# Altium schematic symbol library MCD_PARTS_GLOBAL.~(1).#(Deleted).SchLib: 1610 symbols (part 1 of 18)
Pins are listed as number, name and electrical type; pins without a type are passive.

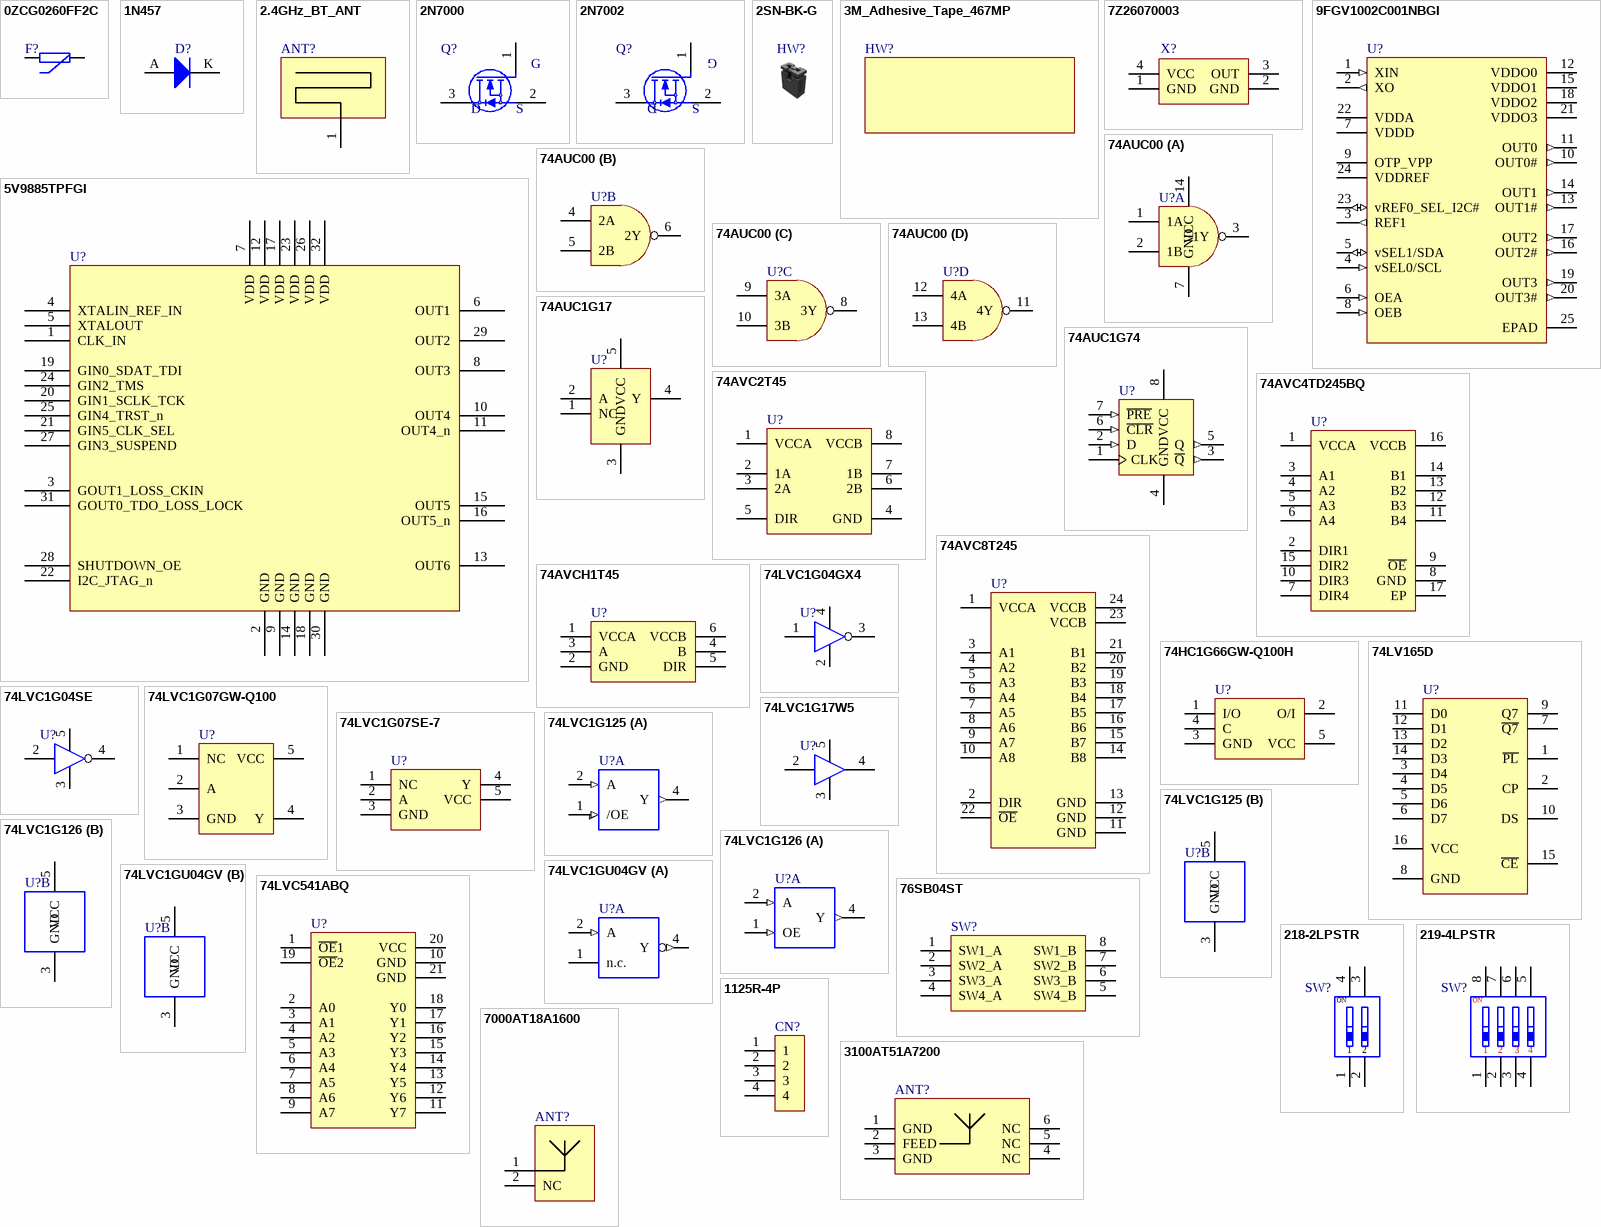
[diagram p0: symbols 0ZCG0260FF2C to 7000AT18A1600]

## 0ZCG0260FF2C
designator F?
pins: 1, 2

## 1N457
designator D?
pins: A, K

## 2.4GHz_BT_ANT
designator ANT?  (no BOM)
pins: 1

## 2N7000
designator Q?
pins: 1 G, 2 S, 3 D

## 2N7002
designator Q?
pins: 1 G, 2 S, 3 D

## 2SN-BK-G
designator HW?

## 3M_Adhesive_Tape_467MP
designator HW?

## 5V9885TPFGI
designator U?
pins: 1 CLK_IN, 2 GND, 3 GOUT1_LOSS_CKIN, 4 XTALIN_REF_IN, 5 XTALOUT, 6 OUT1, 7 VDD, 8 OUT3, 9 GND, 10 OUT4, 11 OUT4_n, 12 VDD, 13 OUT6, 14 GND, 15 OUT5, 16 OUT5_n, 17 VDD, 18 GND, 19 GIN0_SDAT_TDI, 20 GIN1_SCLK_TCK, 21 GIN5_CLK_SEL, 22 I2C_JTAG_n, 23 VDD, 24 GIN2_TMS, 25 GIN4_TRST_n, 26 VDD, 27 GIN3_SUSPEND, 28 SHUTDOWN_OE, 29 OUT2, 30 GND, 31 GOUT0_TDO_LOSS_LOCK, 32 VDD

## 7Z26070003
designator X?
pins: 1 GND, 2 GND, 3 OUT, 4 VCC

## 9FGV1002C001NBGI
designator U?
pins: 1 XIN (in), 2 XO (out), 3 REF1 (out), 4 vSEL0/SCL (in), 5 vSEL1/SDA (io), 6 OEA (in), 7 VDDD (power), 8 OEB (in), 9 OTP_VPP (power), 10 OUT0# (out), 11 OUT0 (out), 12 VDDO0 (power), 13 OUT1# (out), 14 OUT1 (out), 15 VDDO1 (power), 16 OUT2# (out), 17 OUT2 (out), 18 VDDO2 (power), 19 OUT3 (out), 20 OUT3# (out), 21 VDDO3 (power), 22 VDDA (power), 23 vREF0_SEL_I2C# (io), 24 VDDREF (power), 25 EPAD (power)

## 74AUC00
designator U?
part A pins: 1 NC hidden, 1 1A, 2 1B, 3 1Y, 7 GND, 14 VCC
part B pins: 4 2A, 5 2B, 6 2Y
part C pins: 8 3Y, 9 3A, 10 3B
part D pins: 11 4Y, 12 4A, 13 4B

## 74AUC1G17
designator U?
pins: 1 NC, 2 A, 3 GND, 4 Y, 5 VCC

## 74AUC1G74
designator U?
pins: 1 CLK, 2 D (in), 3 ~{Q} (out), 4 GND, 5 Q (out), 6 ~{CLR} (in), 7 ~{PRE} (in), 8 VCC (power)

## 74AVC2T45
designator U?
pins: 1 VCCA, 2 1A, 3 2A, 4 GND, 5 DIR, 6 2B, 7 1B, 8 VCCB

## 74AVC4TD245BQ
designator U?
pins: 1 VCCA, 2 DIR1, 3 A1, 4 A2, 5 A3, 6 A4, 7 DIR4, 8 GND, 9 ~{OE}, 10 DIR3, 11 B4, 12 B3, 13 B2, 14 B1, 15 DIR2, 16 VCCB, 17 EP

## 74AVC8T245
designator U?
pins: 1 VCCA, 2 DIR, 3 A1, 4 A2, 5 A3, 6 A4, 7 A5, 8 A6, 9 A7, 10 A8, 11 GND, 12 GND, 13 GND, 14 B8, 15 B7, 16 B6, 17 B5, 18 B4, 19 B3, 20 B2, 21 B1, 22 ~{OE}, 23 VCCB, 24 VCCB

## 74AVCH1T45
designator U?
pins: 1 VCCA, 2 GND, 3 A, 4 B, 5 DIR, 6 VCCB

## 74HC1G66GW-Q100H
designator U?
pins: 1 I/O, 2 O/I, 3 GND, 4 C, 5 VCC

## 74LV165D
designator U?
pins: 1 ~{PL}, 2 CP, 3 D4, 4 D5, 5 D6, 6 D7, 7 ~{Q7}, 8 GND, 9 Q7, 10 DS, 11 D0, 12 D1, 13 D2, 14 D3, 15 ~{CE}, 16 VCC

## 74LVC1G04GX4
designator U?
pins: 1 NC hidden, 1 A, 2 GND, 3 Y, 4 VCC

## 74LVC1G04SE
designator U?
pins: 1 NC hidden, 2 A, 3 GND, 4 Y, 5 VCC

## 74LVC1G07GW-Q100
designator U?
pins: 1 NC, 2 A, 3 GND, 4 Y, 5 VCC

## 74LVC1G07SE-7
designator U?
pins: 1 NC, 2 A, 3 GND, 4 Y, 5 VCC

## 74LVC1G17W5
designator U?
pins: 1 NC hidden, 2 A, 3 GND, 4 Y, 5 VCC

## 74LVC1G125
designator U?
part A pins: 1 /OE (in), 2 A (in), 4 Y (out)
part B pins: 3 GND (power), 5 VCC

## 74LVC1G126
designator U?
part A pins: 1 OE (in), 2 A (in), 4 Y (out)
part B pins: 3 GND (power), 5 VCC

## 74LVC1GU04GV
designator U?
part A pins: 1 n.c., 2 A (in), 4 Y (out)
part B pins: 3 GND (power), 5 VCC (power)

## 74LVC541ABQ
designator U?
pins: 1 ~{OE}1, 2 A0, 3 A1, 4 A2, 5 A3, 6 A4, 7 A5, 8 A6, 9 A7, 10 GND, 11 Y7, 12 Y6, 13 Y5, 14 Y4, 15 Y3, 16 Y2, 17 Y1, 18 Y0, 19 ~{OE}2, 20 VCC, 21 GND

## 76SB04ST
designator SW?
pins: 1 SW1_A, 2 SW2_A, 3 SW3_A, 4 SW4_A, 5 SW4_B, 6 SW3_B, 7 SW2_B, 8 SW1_B

## 218-2LPSTR
designator SW?
pins: 1, 2, 3, 4

## 219-4LPSTR
designator SW?
pins: 1, 2, 3, 4, 5, 6, 7, 8

## 1125R-4P
designator CN?
pins: 1, 2, 3, 4

## 3100AT51A7200
designator ANT?
pins: 1 GND, 2 FEED, 3 GND, 4 NC, 5 NC, 6 NC

## 7000AT18A1600
designator ANT?
pins: 1, 2 NC

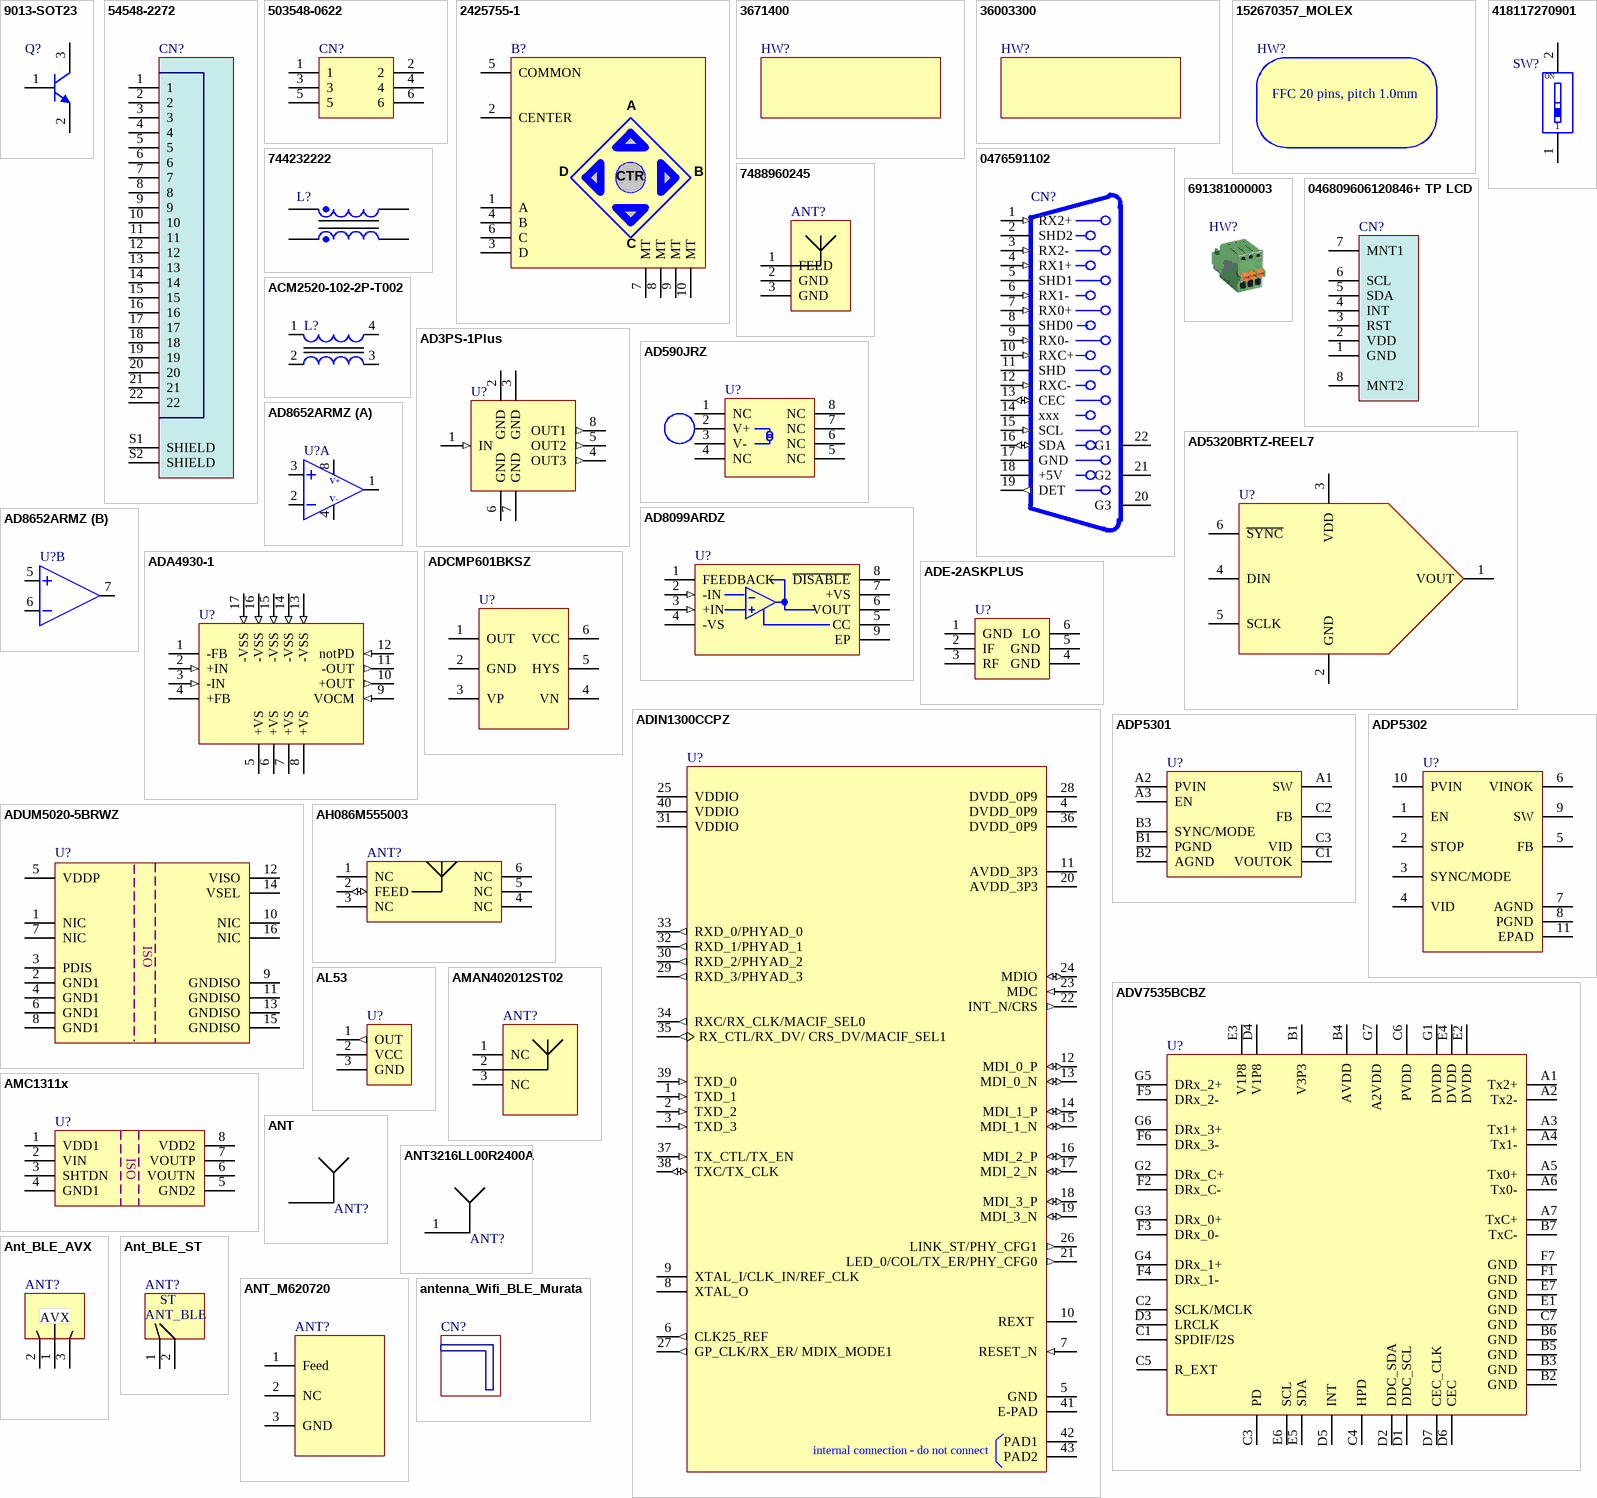
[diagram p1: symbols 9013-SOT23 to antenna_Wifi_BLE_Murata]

## 9013-SOT23
designator Q?
pins: 1 B, 2 E, 3 C

## 54548-2272
designator CN?
pins: 1, 2, 3, 4, 5, 6, 7, 8, 9, 10, 11, 12, 13, 14, 15, 16, 17, 18, 19, 20, 21, 22, S1 SHIELD, S2 SHIELD

## 503548-0622
designator CN?
pins: 1, 2, 3, 4, 5, 6

## 2425755-1
designator B?
pins: 1 A, 2 CENTER, 3 D, 4 B, 5 COMMON, 6 C, 7 MT, 8 MT, 9 MT, 10 MT

## 3671400
designator HW?

## 36003300
designator HW?

## 152670357_MOLEX
designator HW?, comment FFC 20 pins, pitch 1.0mm  (mechanical)

## 0476591102
designator CN?
pins: 1 RX2+ (in), 2 SHD2, 3 RX2- (in), 4 RX1+ (in), 5 SHD1, 6 RX1- (in), 7 RX0+ (in), 8 SHD0, 9 RX0- (in), 10 RXC+ (in), 11 SHD, 12 RXC- (in), 13 CEC (io), 14 xxx, 15 SCL (in), 16 SDA (io), 17 GND, 18 +5V (power), 19 DET (out), 20 G3, 21 G2, 22 G1

## 744232222
designator L?
pins: 1, 2, 3, 4

## 7488960245
designator ANT?
pins: 1 FEED, 2 GND, 3 GND

## 418117270901
designator SW?
pins: 1, 2

## 691381000003
designator HW?

## 046809606120846+ TP LCD
designator CN?
pins: 1 GND, 2 VDD, 3 RST, 4 INT, 5 SDA, 6 SCL, 7 MNT1, 8 MNT2

## ACM2520-102-2P-T002
designator L?
pins: 1, 2, 3, 4

## AD3PS-1Plus
designator U?
pins: 1 IN (in), 2 GND (power), 3 GND (power), 4 OUT3 (out), 5 OUT2 (out), 6 GND (power), 7 GND (power), 8 OUT1 (out)

## AD590JRZ
designator U?
pins: 1 NC, 2 V+, 3 V-, 4 NC, 5 NC, 6 NC, 7 NC, 8 NC

## AD5320BRTZ-REEL7
designator U?
pins: 1 VOUT, 2 GND, 3 VDD, 4 DIN, 5 SCLK, 6 ~{SYNC}

## AD8099ARDZ
designator U?
pins: 1 FEEDBACK, 2 -IN (in), 3 +IN (in), 4 -VS, 5 CC, 6 VOUT, 7 +VS, 8 ~{DISABLE}, 9 EP

## AD8652ARMZ
designator U?
part A pins: 1, 2, 3, 4, 8
part B pins: 5, 6, 7

## ADA4930-1
designator U?
pins: 1 -FB, 2 +IN (in), 3 -IN (in), 4 +FB, 5 +VS, 6 +VS, 7 +VS, 8 +VS, 9 VOCM (in), 10 +OUT (out), 11 -OUT (out), 12 notPD (in), 13 -VSS (in), 14 -VSS (in), 15 -VSS (in), 16 -VSS (in), 17 -VSS (in)

## ADCMP601BKSZ
designator U?
pins: 1 OUT, 2 GND, 3 VP, 4 VN, 5 HYS, 6 VCC

## ADE-2ASKPLUS
designator U?
pins: 1 GND, 2 IF, 3 RF, 4 GND, 5 GND, 6 LO

## ADIN1300CCPZ
designator U?
pins: 1 TXD_1 (in), 2 TXD_2 (in), 3 TXD_3 (in), 4 DVDD_0P9 (power), 5 GND (power), 6 CLK25_REF (out), 7 RESET_N (in), 8 XTAL_O, 9 XTAL_I/CLK_IN/REF_CLK, 10 REXT , 11 AVDD_3P3 (power), 12 MDI_0_P (io), 13 MDI_0_N (io), 14 MDI_1_P (io), 15 MDI_1_N (io), 16 MDI_2_P (io), 17 MDI_2_N (io), 18 MDI_3_P (io), 19 MDI_3_N (io), 20 AVDD_3P3 (power), 21 LED_0/COL/TX_ER/PHY_CFG0 (out), 22 INT_N/CRS (out), 23 MDC (in), 24 MDIO (io), 25 VDDIO (power), 26 LINK_ST/PHY_CFG1 (out), 27 GP_CLK/RX_ER/ MDIX_MODE1  (out), 28 DVDD_0P9 (power), 29 RXD_3/PHYAD_3 (out), 30 RXD_2/PHYAD_2 (out), 31 VDDIO (power), 32 RXD_1/PHYAD_1 (out), 33 RXD_0/PHYAD_0 (out), 34 RXC/RX_CLK/MACIF_SEL0 (out), 35 RX_CTL/RX_DV/ CRS_DV/MACIF_SEL1 (out), 36 DVDD_0P9 (power), 37 TX_CTL/TX_EN  (in), 38 TXC/TX_CLK  (io), 39 TXD_0 (in), 40 VDDIO (power), 41 E-PAD (power), 42 PAD1 (power), 43 PAD2 (power)

## ADP5301
designator U?
pins: A1 SW, A2 PVIN, A3 EN, B1 PGND, B2 AGND, B3 SYNC/MODE, C1 VOUTOK, C2 FB, C3 VID

## ADP5302
designator U?
pins: 1 EN, 2 STOP, 3 SYNC/MODE, 4 VID, 5 FB, 6 VINOK, 7 AGND, 8 PGND, 9 SW, 10 PVIN, 11 EPAD

## ADUM5020-5BRWZ
designator U?
pins: 1 NIC, 2 GND1, 3 PDIS, 4 GND1, 5 VDDP, 6 GND1, 7 NIC, 8 GND1, 9 GNDISO, 10 NIC, 11 GNDISO, 12 VISO, 13 GNDISO, 14 VSEL, 15 GNDISO, 16 NIC

## ADV7535BCBZ
designator U?
pins: A1 Tx2+, A2 Tx2-, A3 Tx1+, A4 Tx1-, A5 Tx0+, A6 Tx0-, A7 TxC+, B1 V3P3, B2 GND, B3 GND, B4 AVDD, B5 GND, B6 GND, B7 TxC-, C1 SPDIF/I2S, C2 SCLK/MCLK, C3 PD, C4 HPD, C5 R_EXT, C6 PVDD, C7 GND, D1 DDC_SCL, D2 DDC_SDA, D3 LRCLK, D4 V1P8, D5 INT, D6 CEC, D7 CEC_CLK, E1 GND, E2 DVDD, E3 V1P8, E4 DVDD, E5 SDA, E6 SCL, E7 GND, F1 GND, F2 DRx_C-, F3 DRx_0-, F4 DRx_1-, F5 DRx_2-, F6 DRx_3-, F7 GND, G1 DVDD, G2 DRx_C+, G3 DRx_0+, G4 DRx_1+, G5 DRx_2+, G6 DRx_3+, G7 A2VDD

## AH086M555003
designator ANT?
pins: 1 NC (hiz), 2 FEED (io), 3 NC (hiz), 4 NC (hiz), 5 NC (hiz), 6 NC (hiz)

## AL53
designator U?
pins: 1 OUT (out), 2 VCC (power), 3 GND (power)

## AMAN402012ST02
designator ANT?
pins: 1 NC, 2, 3 NC

## AMC1311x
designator U?
pins: 1 VDD1, 2 VIN, 3 SHTDN, 4 GND1, 5 GND2, 6 VOUTN, 7 VOUTP, 8 VDD2

## ANT
designator ANT?

## ANT3216LL00R2400A
designator ANT?
pins: 1

## Ant_BLE_AVX
designator ANT?
pins: 1, 2, 3

## Ant_BLE_ST
designator ANT?
pins: 1, 2

## ANT_M620720
designator ANT?
pins: 1 Feed, 2 NC, 3 GND

## antenna_Wifi_BLE_Murata
designator CN?

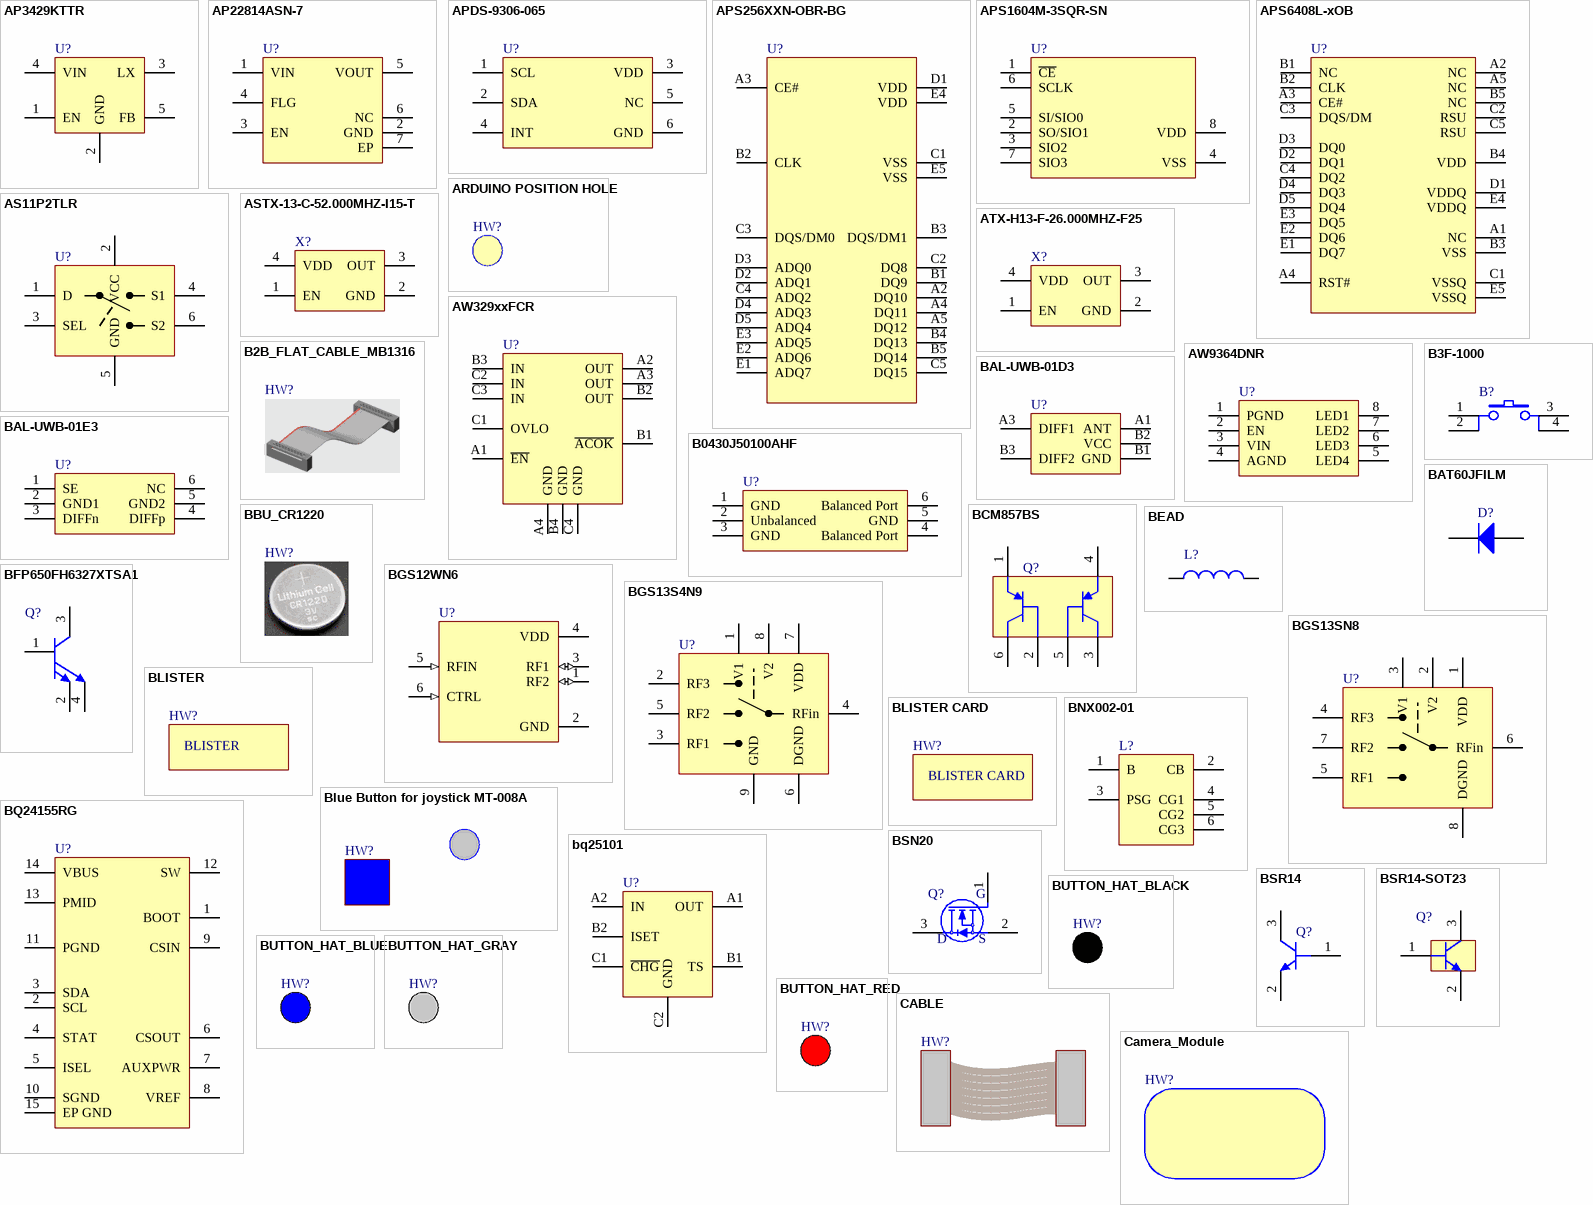
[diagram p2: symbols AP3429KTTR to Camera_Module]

## AP3429KTTR
designator U?
pins: 1 EN, 2 GND, 3 LX, 4 VIN, 5 FB

## AP22814ASN-7
designator U?
pins: 1 VIN, 2 GND, 3 EN, 4 FLG, 5 VOUT, 6 NC, 7 EP

## APDS-9306-065
designator U?
pins: 1 SCL, 2 SDA, 3 VDD, 4 INT, 5 NC, 6 GND

## APS256XXN-OBR-BG
designator U?
pins: A2 DQ10, A3 CE#, A4 DQ11, A5 DQ12, B1 DQ9, B2 CLK, B3 DQS/DM1, B4 DQ13, B5 DQ14, C1 VSS, C2 DQ8, C3 DQS/DM0, C4 ADQ2, C5 DQ15, D1 VDD, D2 ADQ1, D3 ADQ0, D4 ADQ3, D5 ADQ4, E1 ADQ7, E2 ADQ6, E3 ADQ5, E4 VDD, E5 VSS

## APS1604M-3SQR-SN
designator U?
pins: 1 ~{CE}, 2 SO/SIO1, 3 SIO2, 4 VSS, 5 SI/SIO0, 6 SCLK, 7 SIO3, 8 VDD

## APS6408L-xOB
designator U?
pins: A1 NC, A2 NC, A3 CE#, A4 RST#, A5 NC, B1 NC, B2 CLK, B3 VSS, B4 VDD, B5 NC, C1 VSSQ, C2 RSU, C3 DQS/DM, C4 DQ2, C5 RSU, D1 VDDQ, D2 DQ1, D3 DQ0, D4 DQ3, D5 DQ4, E1 DQ7, E2 DQ6, E3 DQ5, E4 VDDQ, E5 VSSQ
1 alternate drawing of the same symbol

## ARDUINO POSITION HOLE
designator HW?  (no BOM)

## AS11P2TLR
designator U?
pins: 1 D, 2 VCC, 3 SEL, 4 S1, 5 GND, 6 S2

## ASTX-13-C-52.000MHZ-I15-T
designator X?
pins: 1 EN, 2 GND, 3 OUT, 4 VDD

## ATX-H13-F-26.000MHZ-F25
designator X?
pins: 1 EN, 2 GND, 3 OUT, 4 VDD

## AW329xxFCR
designator U?
pins: A1 ~{EN}, A2 OUT, A3 OUT, A4 GND, B1 ~{ACOK}, B2 OUT, B3 IN, B4 GND, C1 OVLO, C2 IN, C3 IN, C4 GND

## AW9364DNR
designator U?
pins: 1 PGND, 2 EN, 3 VIN, 4 AGND, 5 LED4, 6 LED3, 7 LED2, 8 LED1

## B2B_FLAT_CABLE_MB1316
designator HW?  (mechanical)

## B3F-1000
designator B?
pins: 1, 2, 3, 4

## B0430J50100AHF
designator U?
pins: 1 GND, 2 Unbalanced, 3 GND, 4 Balanced Port, 5 GND, 6 Balanced Port

## BAL-UWB-01D3
designator U?
pins: A1 ANT, A3 DIFF1, B1 GND, B2 VCC, B3 DIFF2

## BAL-UWB-01E3
designator U?
pins: 1 SE, 2 GND1, 3 DIFFn, 4 DIFFp, 5 GND2, 6 NC

## BAT60JFILM
designator D?
pins: 1 A, 2 K

## BBU_CR1220
designator HW?  (mechanical)

## BCM857BS
designator Q?
pins: 1 E1, 2 B1, 3 C2, 4 E2, 5 B2, 6 C1

## BEAD
designator L?
pins: 1, 2

## BFP650FH6327XTSA1
designator Q?
pins: 1 B, 2 E, 3 C, 4 E

## BGS12WN6
designator U?
pins: 1 RF2 (io), 2 GND (power), 3 RF1 (io), 4 VDD (power), 5 RFIN (in), 6 CTRL (in)

## BGS13S4N9
designator U?
pins: 1 V1, 2 RF3, 3 RF1, 4 RFin, 5 RF2, 6 DGND, 7 VDD, 8 V2, 9 GND

## BGS13SN8
designator U?
pins: 1 VDD, 2 V2, 3 V1, 4 RF3, 5 RF1, 6 RFin, 7 RF2, 8 DGND

## BLISTER
designator HW?  (no BOM)

## BLISTER CARD
designator HW?  (no BOM)

## Blue Button for joystick MT-008A
designator HW?  (mechanical)

## BNX002-01
designator L?
pins: 1 B, 2 CB, 3 PSG, 4 CG1, 5 CG2, 6 CG3

## BQ24155RG
designator U?
pins: 1 BOOT, 2 SCL, 3 SDA, 4 STAT, 5 ISEL, 6 CSOUT, 7 AUXPWR, 8 VREF, 9 CSIN, 10 SGND, 11 PGND, 12 SW, 13 PMID, 14 VBUS, 15 EP GND

## bq25101
designator U?
pins: A1 OUT, A2 IN, B1 TS, B2 ISET, C1 ~{CHG}, C2 GND

## BSN20
designator Q?
pins: 1 G, 2 S, 3 D

## BSR14
designator Q?
pins: 1 B, 2 E, 3 C

## BSR14-SOT23
designator Q?
pins: 1 B, 2 E, 3 C

## BUTTON_HAT_BLACK
designator HW?  (mechanical)

## BUTTON_HAT_BLUE
designator HW?  (mechanical)

## BUTTON_HAT_GRAY
designator HW?  (mechanical)

## BUTTON_HAT_RED
designator HW?  (mechanical)

## CABLE
designator HW?  (mechanical)

## Camera_Module
designator HW?

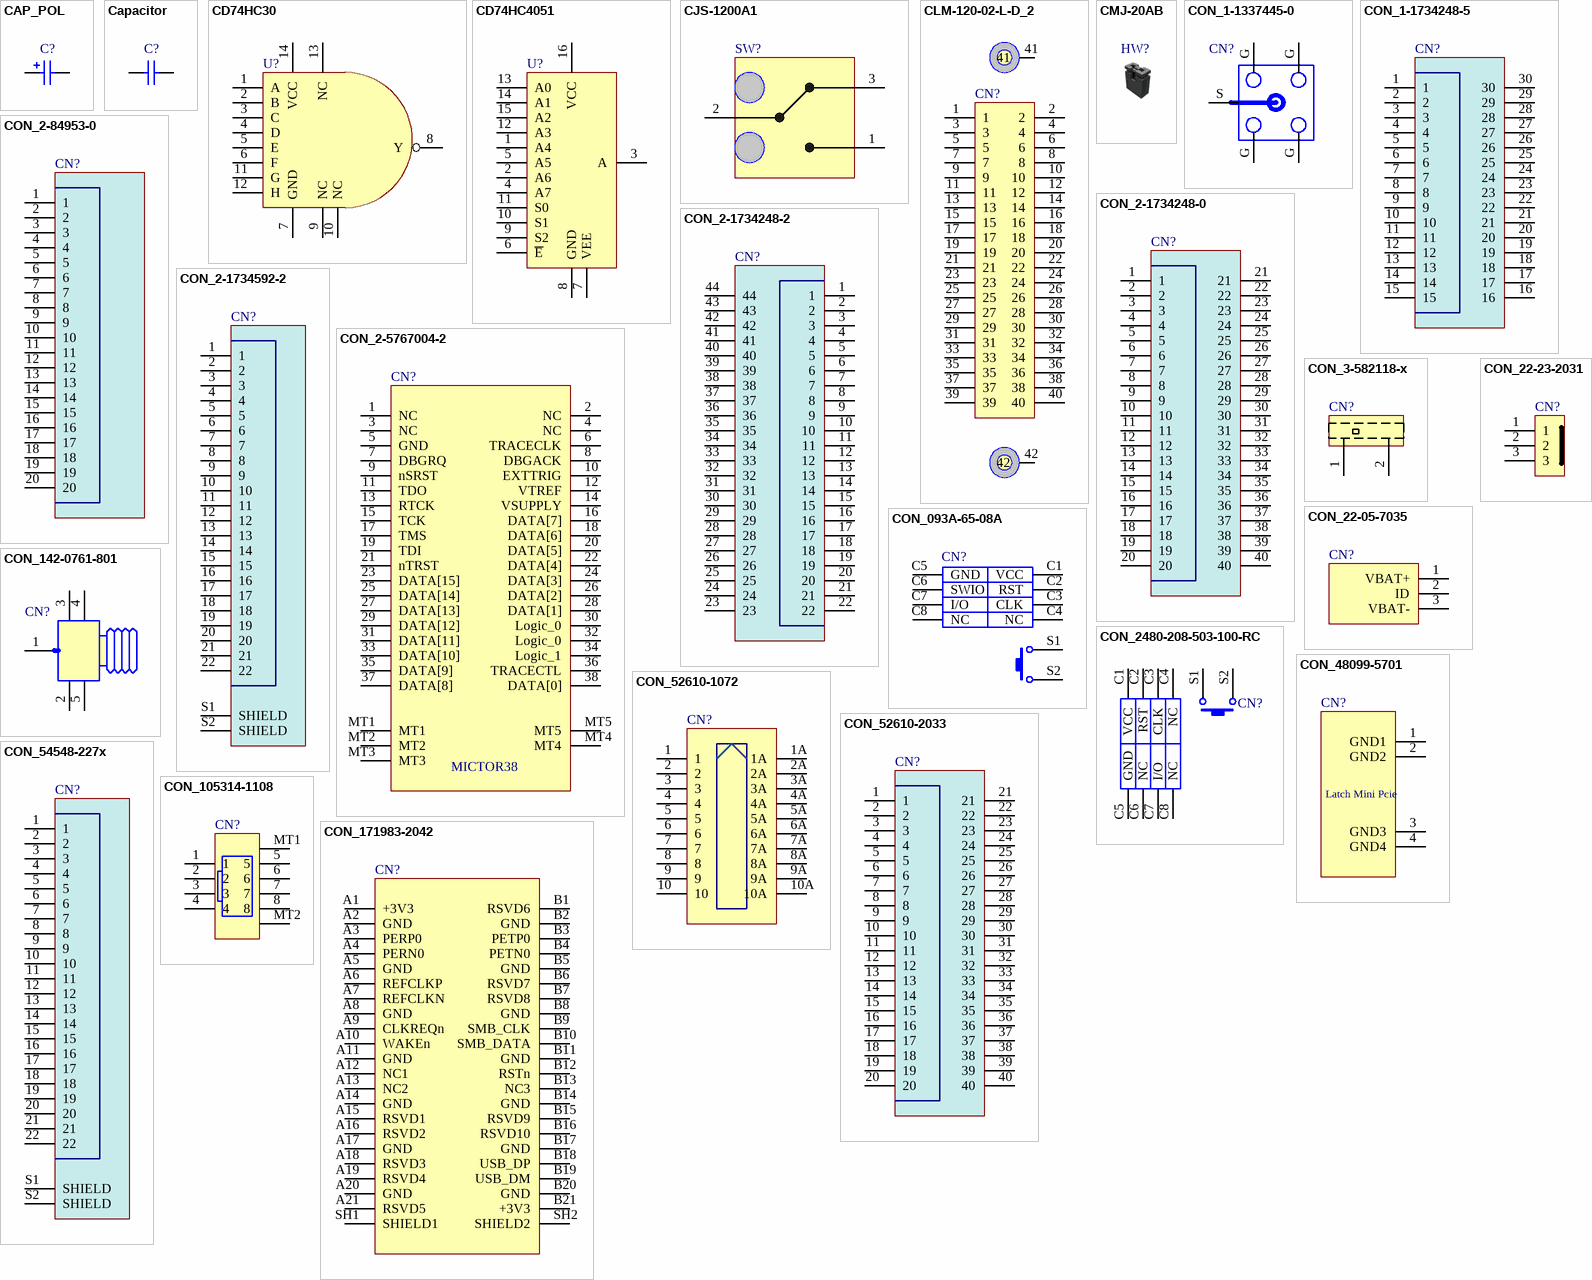
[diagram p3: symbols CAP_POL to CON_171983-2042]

## CAP_POL
designator C?
pins: 1, 2

## Capacitor
designator C?
pins: 1, 2

## CD74HC30
designator U?
pins: 1 NC hidden, 1 A, 2 B, 3 C, 4 D, 5 E, 6 F, 7 GND, 8 Y, 9 NC, 10 NC, 11 G, 12 H, 13 NC, 14 VCC

## CD74HC4051
designator U?
pins: 1 NC hidden, 1 A4, 2 A6, 3 A, 4 A7, 5 A5, 6 ~{E}, 7 VEE, 8 GND, 9 S2, 10 S1, 11 S0, 12 A3, 13 A0, 14 A1, 15 A2, 16 VCC

## CJS-1200A1
designator SW?
pins: 1, 2, 3

## CLM-120-02-L-D_2
designator CN?
pins: 1, 2, 3, 4, 5, 6, 7, 8, 9, 10, 11, 12, 13, 14, 15, 16, 17, 18, 19, 20, 21, 22, 23, 24, 25, 26, 27, 28, 29, 30, 31, 32, 33, 34, 35, 36, 37, 38, 39, 40, 41, 42

## CMJ-20AB
designator HW?

## CON_1-1337445-0
designator CN?
pins: G, G, G, G, S

## CON_1-1734248-5
designator CN?
pins: 1, 2, 3, 4, 5, 6, 7, 8, 9, 10, 11, 12, 13, 14, 15, 16, 17, 18, 19, 20, 21, 22, 23, 24, 25, 26, 27, 28, 29, 30

## CON_2-84953-0
designator CN?
pins: 1, 2, 3, 4, 5, 6, 7, 8, 9, 10, 11, 12, 13, 14, 15, 16, 17, 18, 19, 20

## CON_2-1734248-0
designator CN?
pins: 1, 2, 3, 4, 5, 6, 7, 8, 9, 10, 11, 12, 13, 14, 15, 16, 17, 18, 19, 20, 21, 22, 23, 24, 25, 26, 27, 28, 29, 30, 31, 32, 33, 34, 35, 36, 37, 38, 39, 40

## CON_2-1734248-2
designator CN?
pins: 1, 2, 3, 4, 5, 6, 7, 8, 9, 10, 11, 12, 13, 14, 15, 16, 17, 18, 19, 20, 21, 22, 23, 24, 25, 26, 27, 28, 29, 30, 31, 32, 33, 34, 35, 36, 37, 38, 39, 40, 41, 42, 43, 44

## CON_2-1734592-2
designator CN?
pins: 1, 2, 3, 4, 5, 6, 7, 8, 9, 10, 11, 12, 13, 14, 15, 16, 17, 18, 19, 20, 21, 22, S1 SHIELD, S2 SHIELD

## CON_2-5767004-2
designator CN?
pins: 1 NC, 2 NC, 3 NC, 4 NC, 5 GND, 6 TRACECLK, 7 DBGRQ, 8 DBGACK, 9 nSRST, 10 EXTTRIG, 11 TDO, 12 VTREF, 13 RTCK, 14 VSUPPLY, 15 TCK, 16 DATA[7], 17 TMS, 18 DATA[6], 19 TDI, 20 DATA[5], 21 nTRST, 22 DATA[4], 23 DATA[15], 24 DATA[3], 25 DATA[14], 26 DATA[2], 27 DATA[13], 28 DATA[1], 29 DATA[12], 30 Logic_0, 31 DATA[11], 32 Logic_0, 33 DATA[10], 34 Logic_1, 35 DATA[9], 36 TRACECTL, 37 DATA[8], 38 DATA[0], MT1, MT2, MT3, MT4, MT5

## CON_3-582118-x
designator CN?
pins: 1, 2

## CON_22-05-7035
designator CN?
pins: 1 VBAT+, 2 ID, 3 VBAT-

## CON_22-23-2031
designator CN?
pins: 1, 2, 3

## CON_093A-65-08A
designator CN?
pins: C1 VCC, C2 RST, C3 CLK, C4 NC, C5 GND, C6 SWIO, C7 I/O, C8 NC, S1, S2

## CON_142-0761-801
designator CN?
pins: 1, 2, 3, 4, 5

## CON_2480-208-503-100-RC
designator CN?
pins: C1 VCC, C2 RST, C3 CLK, C4 NC, C5 GND, C6 NC, C7 I/O, C8 NC, S1 9, S2 10

## CON_48099-5701
designator CN?  (mechanical)
pins: 1 GND1, 2 GND2, 3 GND3, 4 GND4

## CON_52610-1072
designator CN?
pins: 1, 1A, 2, 2A, 3, 3A, 4, 4A, 5, 5A, 6, 6A, 7, 7A, 8, 8A, 9, 9A, 10, 10A

## CON_52610-2033
designator CN?
pins: 1, 2, 3, 4, 5, 6, 7, 8, 9, 10, 11, 12, 13, 14, 15, 16, 17, 18, 19, 20, 21, 22, 23, 24, 25, 26, 27, 28, 29, 30, 31, 32, 33, 34, 35, 36, 37, 38, 39, 40

## CON_54548-227x
designator CN?
pins: 1, 2, 3, 4, 5, 6, 7, 8, 9, 10, 11, 12, 13, 14, 15, 16, 17, 18, 19, 20, 21, 22, S1 SHIELD, S2 SHIELD

## CON_105314-1108
designator CN?
pins: 1, 2, 3, 4, 5, 6, 7, 8, MT1, MT2

## CON_171983-2042
designator CN?
pins: A1 +3V3, A2 GND, A3 PERP0, A4 PERN0, A5 GND, A6 REFCLKP, A7 REFCLKN, A8 GND, A9 CLKREQn, A10 WAKEn, A11 GND, A12 NC1, A13 NC2, A14 GND, A15 RSVD1, A16 RSVD2, A17 GND, A18 RSVD3, A19 RSVD4, A20 GND, A21 RSVD5, B1 RSVD6, B2 GND, B3 PETP0, B4 PETN0, B5 GND, B6 RSVD7, B7 RSVD8, B8 GND, B9 SMB_CLK, B10 SMB_DATA, B11 GND, B12 RSTn, B13 NC3, B14 GND, B15 RSVD9, B16 RSVD10, B17 GND, B18 USB_DP, B19 USB_DM, B20 GND, B21 +3V3, SH1 SHIELD1, SH2 SHIELD2

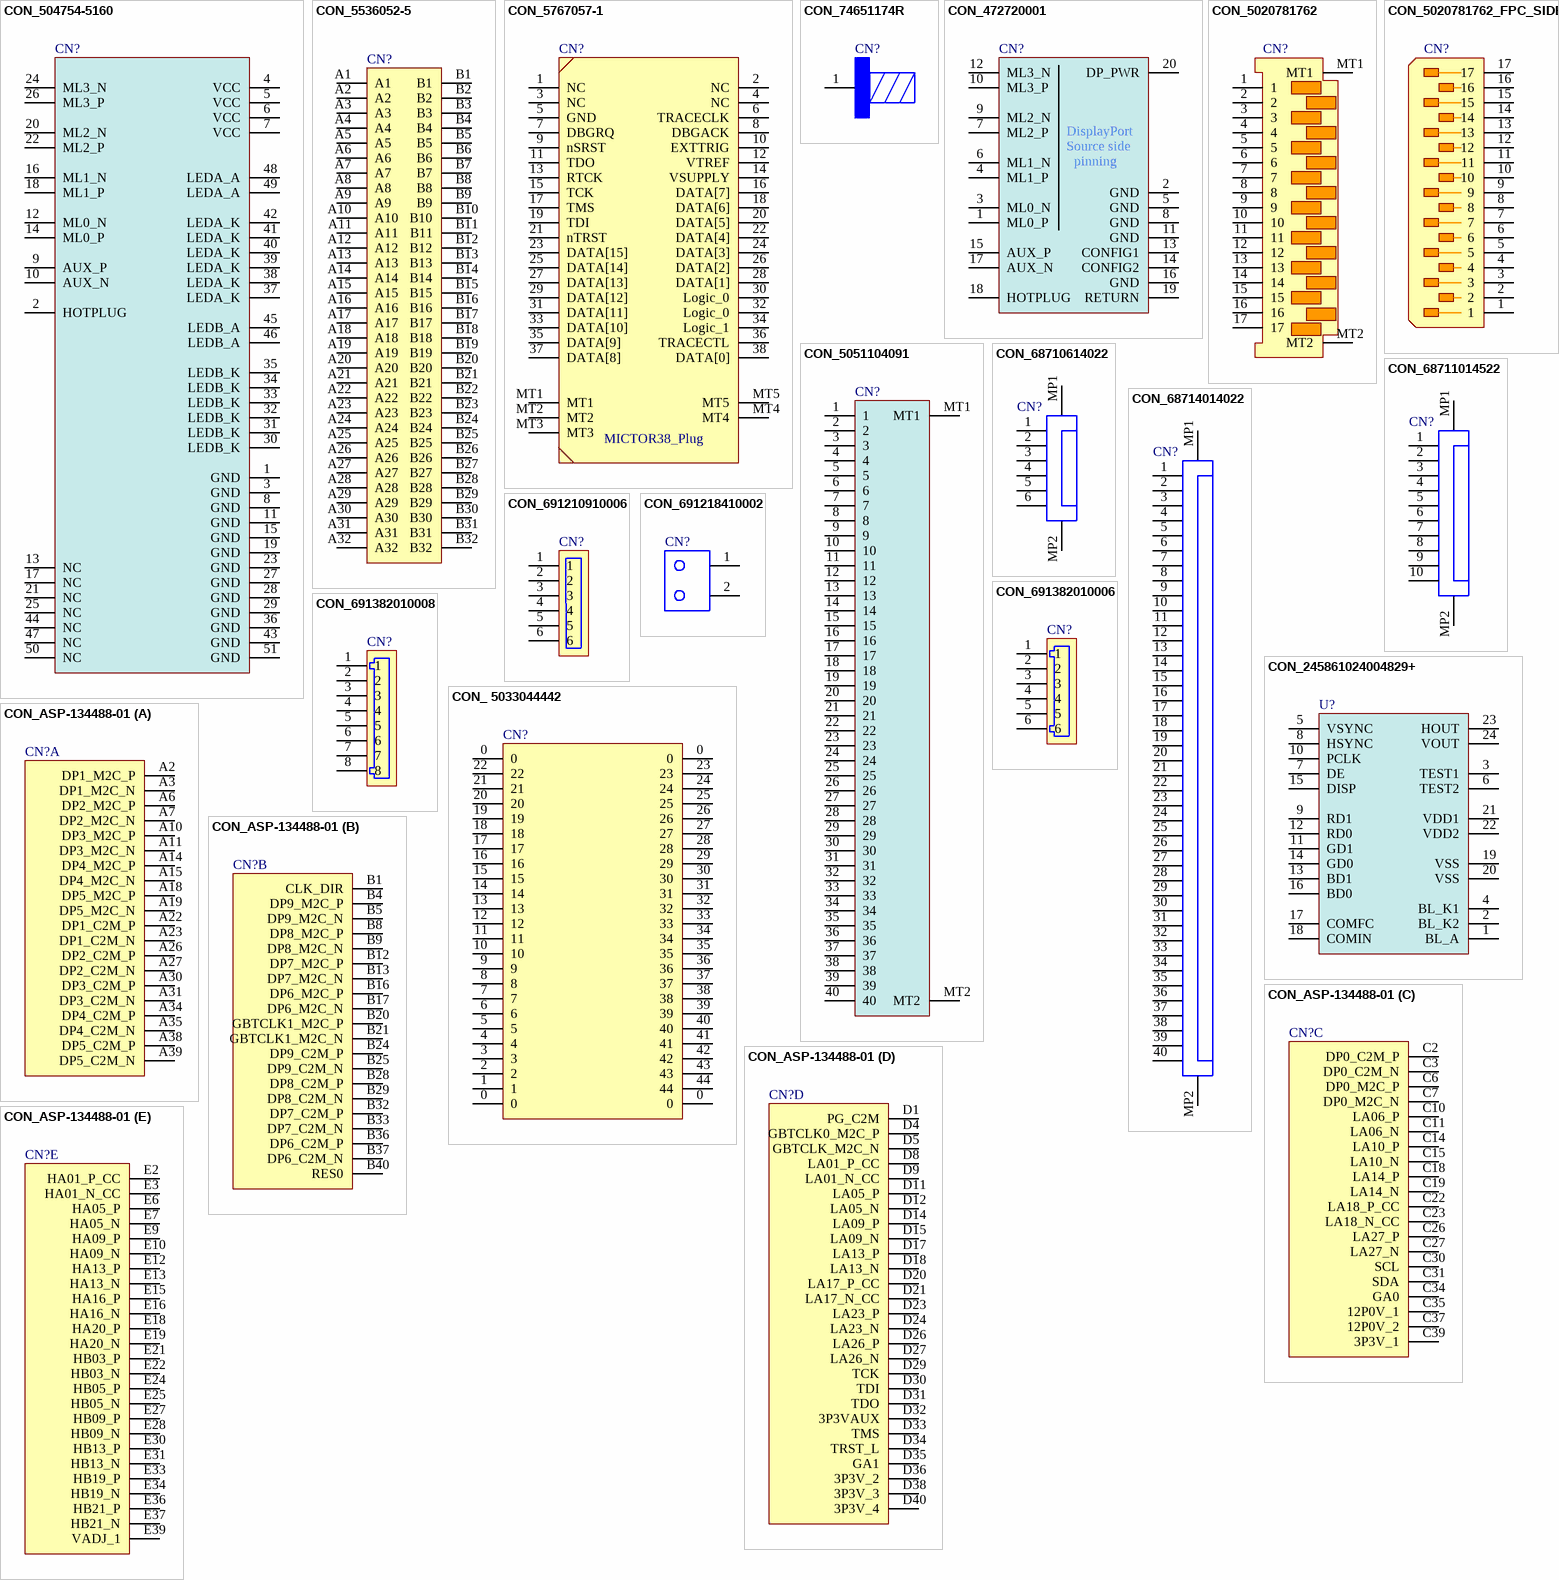
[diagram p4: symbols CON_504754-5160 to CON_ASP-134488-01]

## CON_504754-5160
designator CN?
pins: 1 GND, 2 HOTPLUG, 3 GND, 4 VCC, 5 VCC, 6 VCC, 7 VCC, 8 GND, 9 AUX_P, 10 AUX_N, 11 GND, 12 ML0_N, 13 NC, 14 ML0_P, 15 GND, 16 ML1_N, 17 NC, 18 ML1_P, 19 GND, 20 ML2_N, 21 NC, 22 ML2_P, 23 GND, 24 ML3_N, 25 NC, 26 ML3_P, 27 GND, 28 GND, 29 GND, 30 LEDB_K, 31 LEDB_K, 32 LEDB_K, 33 LEDB_K, 34 LEDB_K, 35 LEDB_K, 36 GND, 37 LEDA_K, 38 LEDA_K, 39 LEDA_K, 40 LEDA_K, 41 LEDA_K, 42 LEDA_K, 43 GND, 44 NC, 45 LEDB_A, 46 LEDB_A, 47 NC, 48 LEDA_A, 49 LEDA_A, 50 NC, 51 GND

## CON_5536052-5
designator CN?
pins: A1, A2, A3, A4, A5, A6, A7, A8, A9, A10, A11, A12, A13, A14, A15, A16, A17, A18, A19, A20, A21, A22, A23, A24, A25, A26, A27, A28, A29, A30, A31, A32, B1, B2, B3, B4, B5, B6, B7, B8, B9, B10, B11, B12, B13, B14, B15, B16, B17, B18, B19, B20, B21, B22, B23, B24, B25, B26, B27, B28, B29, B30, B31, B32

## CON_5767057-1
designator CN?
pins: 1 NC, 2 NC, 3 NC, 4 NC, 5 GND, 6 TRACECLK, 7 DBGRQ, 8 DBGACK, 9 nSRST, 10 EXTTRIG, 11 TDO, 12 VTREF, 13 RTCK, 14 VSUPPLY, 15 TCK, 16 DATA[7], 17 TMS, 18 DATA[6], 19 TDI, 20 DATA[5], 21 nTRST, 22 DATA[4], 23 DATA[15], 24 DATA[3], 25 DATA[14], 26 DATA[2], 27 DATA[13], 28 DATA[1], 29 DATA[12], 30 Logic_0, 31 DATA[11], 32 Logic_0, 33 DATA[10], 34 Logic_1, 35 DATA[9], 36 TRACECTL, 37 DATA[8], 38 DATA[0], MT1, MT2, MT3, MT4, MT5

## CON_74651174R
designator CN?
pins: 1

## CON_472720001
designator CN?
pins: 1 ML0_P, 2 GND, 3 ML0_N, 4 ML1_P, 5 GND, 6 ML1_N, 7 ML2_P, 8 GND, 9 ML2_N, 10 ML3_P, 11 GND, 12 ML3_N, 13 CONFIG1, 14 CONFIG2, 15 AUX_P, 16 GND, 17 AUX_N, 18 HOTPLUG, 19 RETURN, 20 DP_PWR
1 alternate drawing of the same symbol

## CON_5020781762
designator CN?
pins: 1, 2, 3, 4, 5, 6, 7, 8, 9, 10, 11, 12, 13, 14, 15, 16, 17, MT1, MT2

## CON_5020781762_FPC_SIDE
designator CN?
pins: 1, 2, 3, 4, 5, 6, 7, 8, 9, 10, 11, 12, 13, 14, 15, 16, 17

## CON_5051104091
designator CN?
pins: 1, 2, 3, 4, 5, 6, 7, 8, 9, 10, 11, 12, 13, 14, 15, 16, 17, 18, 19, 20, 21, 22, 23, 24, 25, 26, 27, 28, 29, 30, 31, 32, 33, 34, 35, 36, 37, 38, 39, 40, MT1, MT2

## CON_68710614022
designator CN?
pins: 1, 2, 3, 4, 5, 6, MP1, MP2

## CON_68711014522
designator CN?
pins: 1, 2, 3, 4, 5, 6, 7, 8, 9, 10, MP1, MP2

## CON_68714014022
designator CN?
pins: 1, 2, 3, 4, 5, 6, 7, 8, 9, 10, 11, 12, 13, 14, 15, 16, 17, 18, 19, 20, 21, 22, 23, 24, 25, 26, 27, 28, 29, 30, 31, 32, 33, 34, 35, 36, 37, 38, 39, 40, MP1, MP2

## CON_691210910006
designator CN?
pins: 1, 2, 3, 4, 5, 6

## CON_691218410002
designator CN?
pins: 1, 2

## CON_691382010006
designator CN?
pins: 1, 2, 3, 4, 5, 6

## CON_691382010008
designator CN?
pins: 1, 2, 3, 4, 5, 6, 7, 8

## CON_245861024004829+
designator U?
pins: 1 BL_A, 2 BL_K2, 3 TEST1, 4 BL_K1, 5 VSYNC, 6 TEST2, 7 DE, 8 HSYNC, 9 RD1, 10 PCLK, 11 GD1, 12 RD0, 13 BD1, 14 GD0, 15 DISP, 16 BD0, 17 COMFC, 18 COMIN, 19 VSS, 20 VSS, 21 VDD1, 22 VDD2, 23 HOUT, 24 VOUT

## CON_ 5033044442
designator CN?
pins: 0, 0, 0, 0, 1, 2, 3, 4, 5, 6, 7, 8, 9, 10, 11, 12, 13, 14, 15, 16, 17, 18, 19, 20, 21, 22, 23, 24, 25, 26, 27, 28, 29, 30, 31, 32, 33, 34, 35, 36, 37, 38, 39, 40, 41, 42, 43, 44

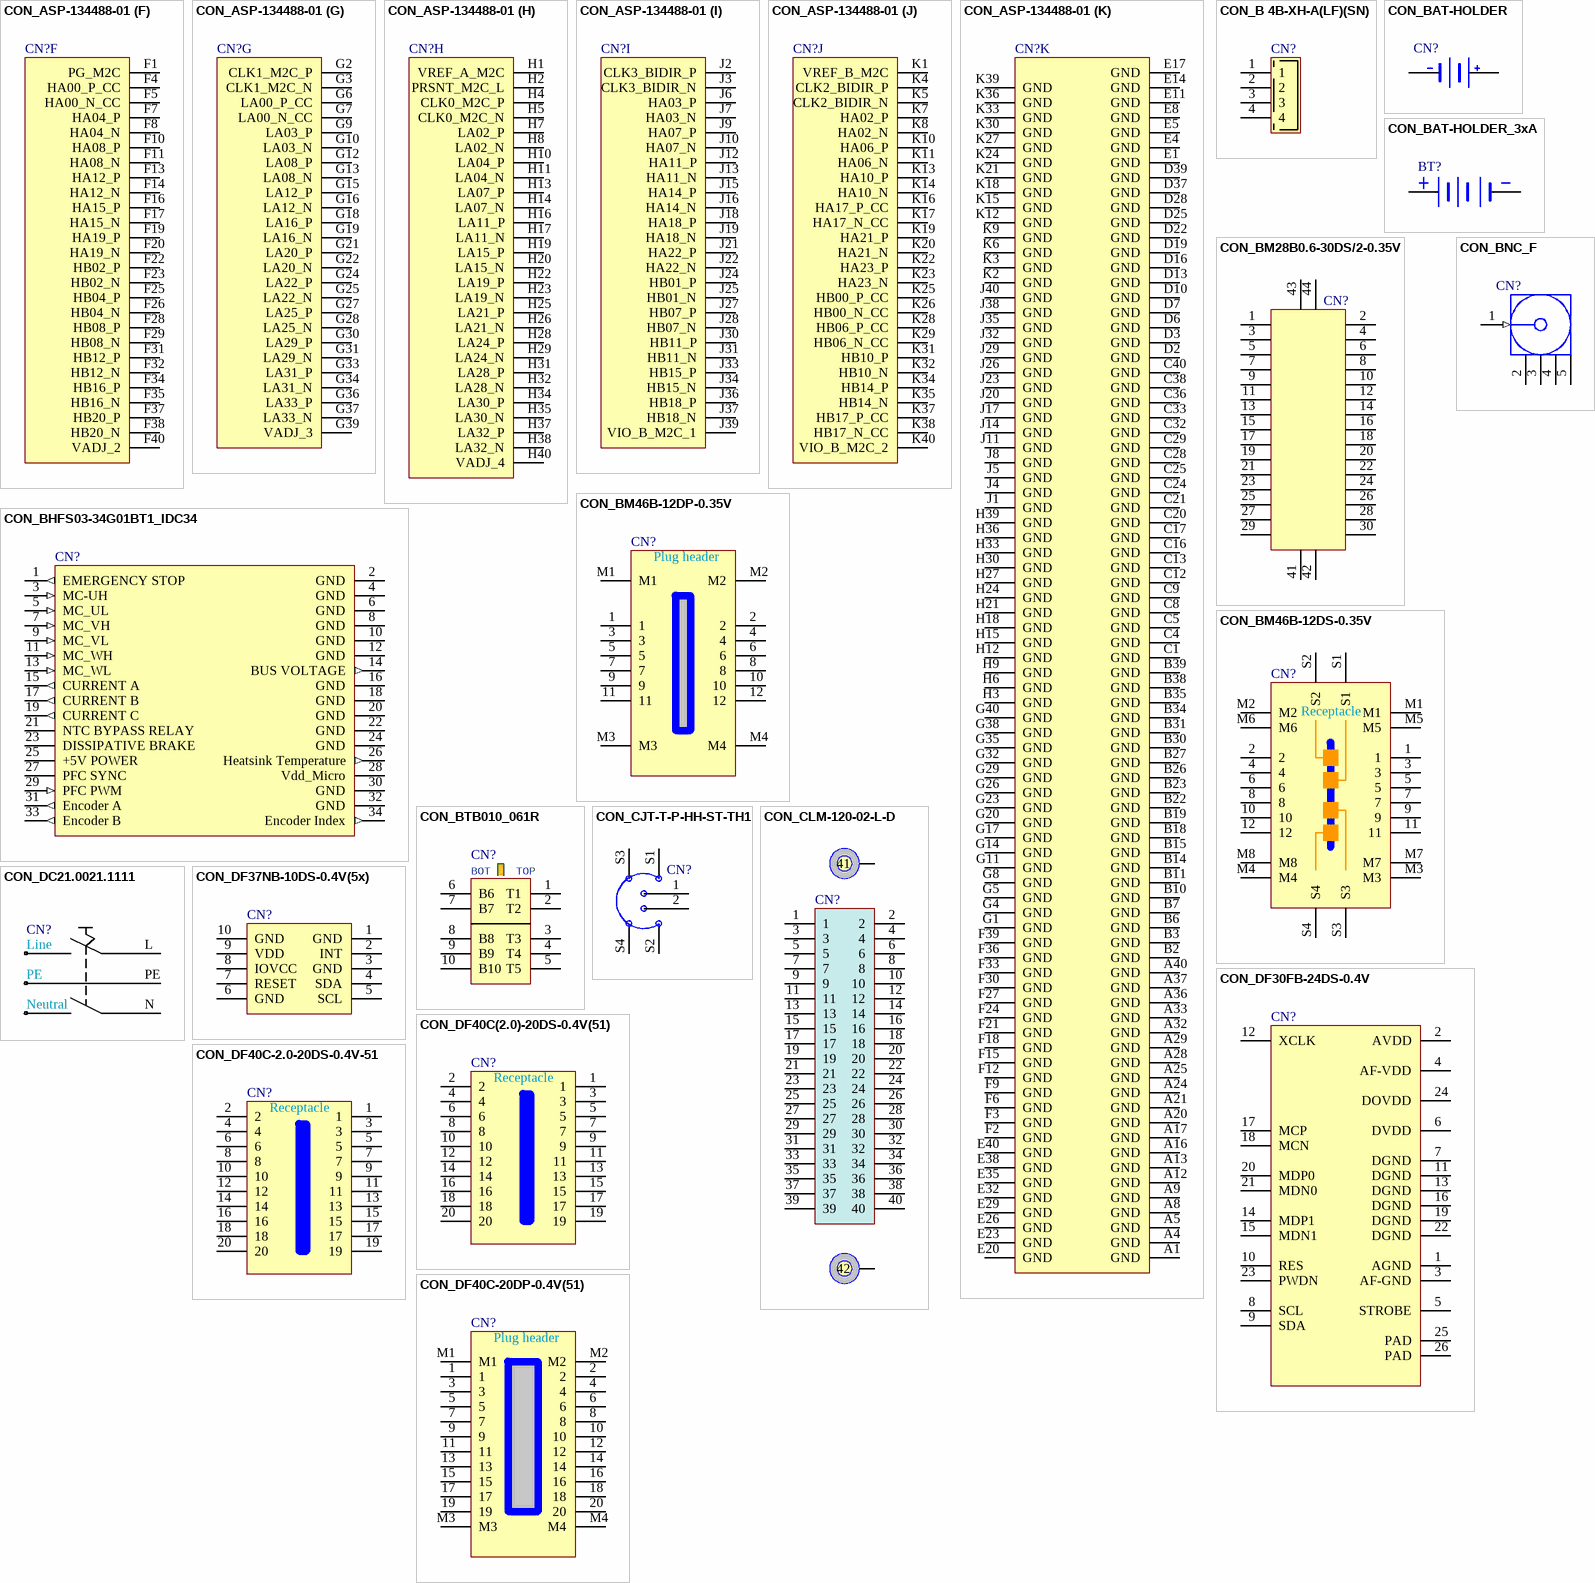
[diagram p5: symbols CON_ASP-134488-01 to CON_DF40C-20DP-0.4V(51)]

## CON_ASP-134488-01
designator CN?
part A pins: A2 DP1_M2C_P, A3 DP1_M2C_N, A6 DP2_M2C_P, A7 DP2_M2C_N, A10 DP3_M2C_P, A11 DP3_M2C_N, A14 DP4_M2C_P, A15 DP4_M2C_N, A18 DP5_M2C_P, A19 DP5_M2C_N, A22 DP1_C2M_P, A23 DP1_C2M_N, A26 DP2_C2M_P, A27 DP2_C2M_N, A30 DP3_C2M_P, A31 DP3_C2M_N, A34 DP4_C2M_P, A35 DP4_C2M_N, A38 DP5_C2M_P, A39 DP5_C2M_N
part B pins: B1 CLK_DIR, B4 DP9_M2C_P, B5 DP9_M2C_N, B8 DP8_M2C_P, B9 DP8_M2C_N, B12 DP7_M2C_P, B13 DP7_M2C_N, B16 DP6_M2C_P, B17 DP6_M2C_N, B20 GBTCLK1_M2C_P, B21 GBTCLK1_M2C_N, B24 DP9_C2M_P, B25 DP9_C2M_N, B28 DP8_C2M_P, B29 DP8_C2M_N, B32 DP7_C2M_P, B33 DP7_C2M_N, B36 DP6_C2M_P, B37 DP6_C2M_N, B40 RES0
part C pins: C2 DP0_C2M_P, C3 DP0_C2M_N, C6 DP0_M2C_P, C7 DP0_M2C_N, C10 LA06_P, C11 LA06_N, C14 LA10_P, C15 LA10_N, C18 LA14_P, C19 LA14_N, C22 LA18_P_CC, C23 LA18_N_CC, C26 LA27_P, C27 LA27_N, C30 SCL, C31 SDA, C34 GA0, C35 12P0V_1, C37 12P0V_2, C39 3P3V_1
part D pins: D1 PG_C2M, D4 GBTCLK0_M2C_P, D5 GBTCLK_M2C_N, D8 LA01_P_CC, D9 LA01_N_CC, D11 LA05_P, D12 LA05_N, D14 LA09_P, D15 LA09_N, D17 LA13_P, D18 LA13_N, D20 LA17_P_CC, D21 LA17_N_CC, D23 LA23_P, D24 LA23_N, D26 LA26_P, D27 LA26_N, D29 TCK, D30 TDI, D31 TDO, D32 3P3VAUX, D33 TMS, D34 TRST_L, D35 GA1, D36 3P3V_2, D38 3P3V_3, D40 3P3V_4
part E pins: E2 HA01_P_CC, E3 HA01_N_CC, E6 HA05_P, E7 HA05_N, E9 HA09_P, E10 HA09_N, E12 HA13_P, E13 HA13_N, E15 HA16_P, E16 HA16_N, E18 HA20_P, E19 HA20_N, E21 HB03_P, E22 HB03_N, E24 HB05_P, E25 HB05_N, E27 HB09_P, E28 HB09_N, E30 HB13_P, E31 HB13_N, E33 HB19_P, E34 HB19_N, E36 HB21_P, E37 HB21_N, E39 VADJ_1
part F pins: F1 PG_M2C, F4 HA00_P_CC, F5 HA00_N_CC, F7 HA04_P, F8 HA04_N, F10 HA08_P, F11 HA08_N, F13 HA12_P, F14 HA12_N, F16 HA15_P, F17 HA15_N, F19 HA19_P, F20 HA19_N, F22 HB02_P, F23 HB02_N, F25 HB04_P, F26 HB04_N, F28 HB08_P, F29 HB08_N, F31 HB12_P, F32 HB12_N, F34 HB16_P, F35 HB16_N, F37 HB20_P, F38 HB20_N, F40 VADJ_2
part G pins: G2 CLK1_M2C_P, G3 CLK1_M2C_N, G6 LA00_P_CC, G7 LA00_N_CC, G9 LA03_P, G10 LA03_N, G12 LA08_P, G13 LA08_N, G15 LA12_P, G16 LA12_N, G18 LA16_P, G19 LA16_N, G21 LA20_P, G22 LA20_N, G24 LA22_P, G25 LA22_N, G27 LA25_P, G28 LA25_N, G30 LA29_P, G31 LA29_N, G33 LA31_P, G34 LA31_N, G36 LA33_P, G37 LA33_N, G39 VADJ_3
part H pins: H1 VREF_A_M2C, H2 PRSNT_M2C_L, H4 CLK0_M2C_P, H5 CLK0_M2C_N, H7 LA02_P, H8 LA02_N, H10 LA04_P, H11 LA04_N, H13 LA07_P, H14 LA07_N, H16 LA11_P, H17 LA11_N, H19 LA15_P, H20 LA15_N, H22 LA19_P, H23 LA19_N, H25 LA21_P, H26 LA21_N, H28 LA24_P, H29 LA24_N, H31 LA28_P, H32 LA28_N, H34 LA30_P, H35 LA30_N, H37 LA32_P, H38 LA32_N, H40 VADJ_4
part I pins: J2 CLK3_BIDIR_P, J3 CLK3_BIDIR_N, J6 HA03_P, J7 HA03_N, J9 HA07_P, J10 HA07_N, J12 HA11_P, J13 HA11_N, J15 HA14_P, J16 HA14_N, J18 HA18_P, J19 HA18_N, J21 HA22_P, J22 HA22_N, J24 HB01_P, J25 HB01_N, J27 HB07_P, J28 HB07_N, J30 HB11_P, J31 HB11_N, J33 HB15_P, J34 HB15_N, J36 HB18_P, J37 HB18_N, J39 VIO_B_M2C_1
part J pins: K1 VREF_B_M2C, K4 CLK2_BIDIR_P, K5 CLK2_BIDIR_N, K7 HA02_P, K8 HA02_N, K10 HA06_P, K11 HA06_N, K13 HA10_P, K14 HA10_N, K16 HA17_P_CC, K17 HA17_N_CC, K19 HA21_P, K20 HA21_N, K22 HA23_P, K23 HA23_N, K25 HB00_P_CC, K26 HB00_N_CC, K28 HB06_P_CC, K29 HB06_N_CC, K31 HB10_P, K32 HB10_N, K34 HB14_P, K35 HB14_N, K37 HB17_P_CC, K38 HB17_N_CC, K40 VIO_B_M2C_2
part K pins: A1 GND, A4 GND, A5 GND, A8 GND, A9 GND, A12 GND, A13 GND, A16 GND, A17 GND, A20 GND, A21 GND, A24 GND, A25 GND, A28 GND, A29 GND, A32 GND, A33 GND, A36 GND, A37 GND, A40 GND, B2 GND, B3 GND, B6 GND, B7 GND, B10 GND, B11 GND, B14 GND, B15 GND, B18 GND, B19 GND, B22 GND, B23 GND, B26 GND, B27 GND, B30 GND, B31 GND, B34 GND, B35 GND, B38 GND, B39 GND, C1 GND, C4 GND, C5 GND, C8 GND, C9 GND, C12 GND, C13 GND, C16 GND, C17 GND, C20 GND, C21 GND, C24 GND, C25 GND, C28 GND, C29 GND, C32 GND, C33 GND, C36 GND, C38 GND, C40 GND, D2 GND, D3 GND, D6 GND, D7 GND, D10 GND, D13 GND, D16 GND, D19 GND, D22 GND, D25 GND, D28 GND, D37 GND, D39 GND, E1 GND, E4 GND, E5 GND, E8 GND, E11 GND, E14 GND, E17 GND, E20 GND, E23 GND, E26 GND, E29 GND, E32 GND, E35 GND, E38 GND, E40 GND, F2 GND, F3 GND, F6 GND, F9 GND, F12 GND, F15 GND, F18 GND, F21 GND, F24 GND, F27 GND, F30 GND, F33 GND, F36 GND, F39 GND, G1 GND, G4 GND, G5 GND, G8 GND, G11 GND, G14 GND, G17 GND, G20 GND, G23 GND, G26 GND, G29 GND, G32 GND, G35 GND, G38 GND, G40 GND, H3 GND, H6 GND, H9 GND, H12 GND, H15 GND, H18 GND, H21 GND, H24 GND, H27 GND, H30 GND, H33 GND, H36 GND, H39 GND, J1 GND, J4 GND, J5 GND, J8 GND, J11 GND, J14 GND, J17 GND, J20 GND, J23 GND, J26 GND, J29 GND, J32 GND, J35 GND, J38 GND, J40 GND, K2 GND, K3 GND, K6 GND, K9 GND, K12 GND, K15 GND, K18 GND, K21 GND, K24 GND, K27 GND, K30 GND, K33 GND, K36 GND, K39 GND

## CON_B 4B-XH-A(LF)(SN)
designator CN?
pins: 1, 2, 3, 4

## CON_BAT-HOLDER
designator CN?
pins: 1 +, 2 -

## CON_BAT-HOLDER_3xA
designator BT?
pins: 1 +, 2 -
2 alternate drawings of the same symbol

## CON_BHFS03-34G01BT1_IDC34
designator CN?
pins: 1 EMERGENCY STOP (out), 2 GND (power), 3 MC-UH (in), 4 GND (power), 5 MC_UL (in), 6 GND (power), 7 MC_VH (in), 8 GND (power), 9 MC_VL (in), 10 GND (power), 11 MC_WH (in), 12 GND (power), 13 MC_WL (in), 14 BUS VOLTAGE (out), 15 CURRENT A (out), 16 GND (power), 17 CURRENT B (out), 18 GND (power), 19 CURRENT C (out), 20 GND (power), 21 NTC BYPASS RELAY, 22 GND (power), 23 DISSIPATIVE BRAKE, 24 GND (power), 25 +5V POWER (power), 26 Heatsink Temperature (out), 27 PFC SYNC, 28 Vdd_Micro (power), 29 PFC PWM (in), 30 GND (power), 31 Encoder A (out), 32 GND (power), 33 Encoder B (out), 34 Encoder Index (out)

## CON_BM28B0.6-30DS/2-0.35V
designator CN?
pins: 1, 2, 3, 4, 5, 6, 7, 8, 9, 10, 11, 12, 13, 14, 15, 16, 17, 18, 19, 20, 21, 22, 23, 24, 25, 26, 27, 28, 29, 30, 41, 42, 43, 44
1 alternate drawing of the same symbol

## CON_BM46B-12DP-0.35V
designator CN?
pins: 1, 2, 3, 4, 5, 6, 7, 8, 9, 10, 11, 12, M1, M2, M3, M4

## CON_BM46B-12DS-0.35V
designator CN?
pins: 1, 2, 3, 4, 5, 6, 7, 8, 9, 10, 11, 12, M1, M2, M3, M4, M5, M6, M7, M8, S1, S2, S3, S4

## CON_BNC_F
designator CN?
pins: 1 Signal (in) "Signal Pin", 2 GND (power), 3 GND (power), 4 GND (power), 5 GND (power)

## CON_BTB010_061R
designator CN?
pins: 1 T1, 2 T2, 3 T3, 4 T4, 5 T5, 6 B6, 7 B7, 8 B8, 9 B9, 10 B10

## CON_CJT-T-P-HH-ST-TH1
designator CN?
pins: 1, 2, S1, S2, S3, S4

## CON_CLM-120-02-L-D
designator CN?
pins: 1, 2, 3, 4, 5, 6, 7, 8, 9, 10, 11, 12, 13, 14, 15, 16, 17, 18, 19, 20, 21, 22, 23, 24, 25, 26, 27, 28, 29, 30, 31, 32, 33, 34, 35, 36, 37, 38, 39, 40, 41, 42

## CON_DC21.0021.1111
designator CN?
pins: L, N, PE

## CON_DF30FB-24DS-0.4V
designator CN?
pins: 1 AGND, 2 AVDD, 3 AF-GND, 4 AF-VDD, 5 STROBE, 6 DVDD, 7 DGND, 8 SCL, 9 SDA, 10 RES, 11 DGND, 12 XCLK, 13 DGND, 14 MDP1, 15 MDN1, 16 DGND, 17 MCP, 18 MCN, 19 DGND, 20 MDP0, 21 MDN0, 22 DGND, 23 PWDN, 24 DOVDD, 25 PAD, 26 PAD

## CON_DF37NB-10DS-0.4V(5x)
designator CN?
pins: 1 GND, 2 INT, 3 GND, 4 SDA, 5 SCL, 6 GND, 7 RESET, 8 IOVCC, 9 VDD, 10 GND

## CON_DF40C(2.0)-20DS-0.4V(51)
designator CN?
pins: 1, 2, 3, 4, 5, 6, 7, 8, 9, 10, 11, 12, 13, 14, 15, 16, 17, 18, 19, 20

## CON_DF40C-2.0-20DS-0.4V-51
designator CN?
pins: 1, 2, 3, 4, 5, 6, 7, 8, 9, 10, 11, 12, 13, 14, 15, 16, 17, 18, 19, 20

## CON_DF40C-20DP-0.4V(51)
designator CN?
pins: 1, 2, 3, 4, 5, 6, 7, 8, 9, 10, 11, 12, 13, 14, 15, 16, 17, 18, 19, 20, M1, M2, M3, M4

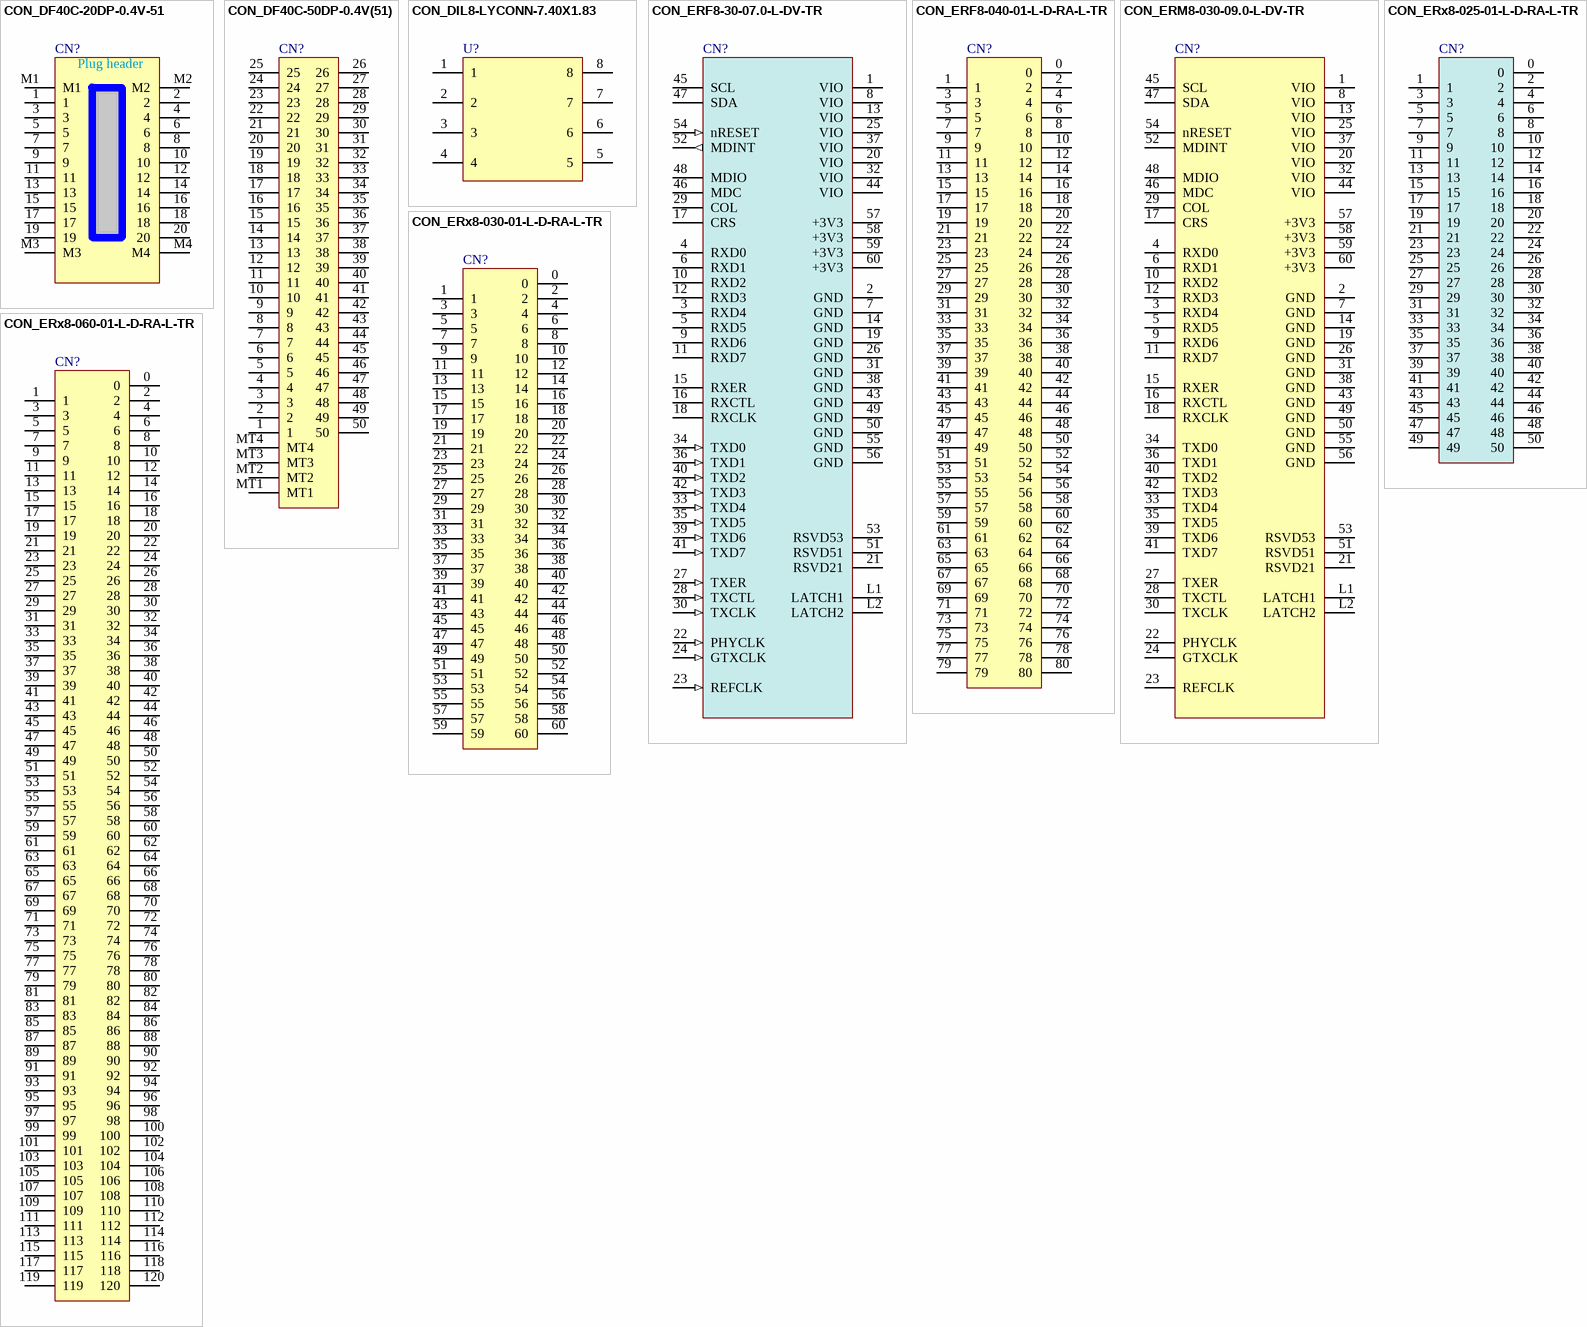
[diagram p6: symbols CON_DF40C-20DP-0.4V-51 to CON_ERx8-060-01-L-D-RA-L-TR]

## CON_DF40C-20DP-0.4V-51
designator CN?
pins: 1, 2, 3, 4, 5, 6, 7, 8, 9, 10, 11, 12, 13, 14, 15, 16, 17, 18, 19, 20, M1, M2, M3, M4

## CON_DF40C-50DP-0.4V(51)
designator CN?
pins: 1, 2, 3, 4, 5, 6, 7, 8, 9, 10, 11, 12, 13, 14, 15, 16, 17, 18, 19, 20, 21, 22, 23, 24, 25, 26, 27, 28, 29, 30, 31, 32, 33, 34, 35, 36, 37, 38, 39, 40, 41, 42, 43, 44, 45, 46, 47, 48, 49, 50, MT1, MT2, MT3, MT4

## CON_DIL8-LYCONN-7.40X1.83
designator U?
pins: 1, 2, 3, 4, 5, 6, 7, 8

## CON_ERF8-30-07.0-L-DV-TR
designator CN?
pins: 1 VIO, 2 GND, 3 RXD4, 4 RXD0, 5 RXD5, 6 RXD1, 7 GND, 8 VIO, 9 RXD6, 10 RXD2, 11 RXD7, 12 RXD3, 13 VIO, 14 GND, 15 RXER, 16 RXCTL, 17 CRS, 18 RXCLK, 19 GND, 20 VIO, 21 RSVD21, 22 PHYCLK (in), 23 REFCLK (in), 24 GTXCLK (in), 25 VIO, 26 GND, 27 TXER (in), 28 TXCTL (in), 29 COL, 30 TXCLK (in), 31 GND, 32 VIO, 33 TXD4 (in), 34 TXD0 (in), 35 TXD5 (in), 36 TXD1 (in), 37 VIO, 38 GND, 39 TXD6 (in), 40 TXD2 (in), 41 TXD7 (in), 42 TXD3 (in), 43 GND, 44 VIO, 45 SCL, 46 MDC, 47 SDA, 48 MDIO, 49 GND, 50 GND, 51 RSVD51, 52 MDINT (out), 53 RSVD53, 54 nRESET (in), 55 GND, 56 GND, 57 +3V3, 58 +3V3, 59 +3V3, 60 +3V3, L1 LATCH1, L2 LATCH2

## CON_ERF8-040-01-L-D-RA-L-TR
designator CN?
pins: 0, 1, 2, 3, 4, 5, 6, 7, 8, 9, 10, 11, 12, 13, 14, 15, 16, 17, 18, 19, 20, 21, 22, 23, 24, 25, 26, 27, 28, 29, 30, 31, 32, 33, 34, 35, 36, 37, 38, 39, 40, 41, 42, 43, 44, 45, 46, 47, 48, 49, 50, 51, 52, 53, 54, 55, 56, 57, 58, 59, 60, 61, 62, 63, 64, 65, 66, 67, 68, 69, 70, 71, 72, 73, 74, 75, 76, 77, 78, 79, 80

## CON_ERM8-030-09.0-L-DV-TR
designator CN?
pins: 1 VIO, 2 GND, 3 RXD4, 4 RXD0, 5 RXD5, 6 RXD1, 7 GND, 8 VIO, 9 RXD6, 10 RXD2, 11 RXD7, 12 RXD3, 13 VIO, 14 GND, 15 RXER, 16 RXCTL, 17 CRS, 18 RXCLK, 19 GND, 20 VIO, 21 RSVD21, 22 PHYCLK, 23 REFCLK, 24 GTXCLK, 25 VIO, 26 GND, 27 TXER, 28 TXCTL, 29 COL, 30 TXCLK, 31 GND, 32 VIO, 33 TXD4, 34 TXD0, 35 TXD5, 36 TXD1, 37 VIO, 38 GND, 39 TXD6, 40 TXD2, 41 TXD7, 42 TXD3, 43 GND, 44 VIO, 45 SCL, 46 MDC, 47 SDA, 48 MDIO, 49 GND, 50 GND, 51 RSVD51, 52 MDINT, 53 RSVD53, 54 nRESET, 55 GND, 56 GND, 57 +3V3, 58 +3V3, 59 +3V3, 60 +3V3, L1 LATCH1, L2 LATCH2

## CON_ERx8-025-01-L-D-RA-L-TR
designator CN?
pins: 0, 1, 2, 3, 4, 5, 6, 7, 8, 9, 10, 11, 12, 13, 14, 15, 16, 17, 18, 19, 20, 21, 22, 23, 24, 25, 26, 27, 28, 29, 30, 31, 32, 33, 34, 35, 36, 37, 38, 39, 40, 41, 42, 43, 44, 45, 46, 47, 48, 49, 50

## CON_ERx8-030-01-L-D-RA-L-TR
designator CN?
pins: 0, 1, 2, 3, 4, 5, 6, 7, 8, 9, 10, 11, 12, 13, 14, 15, 16, 17, 18, 19, 20, 21, 22, 23, 24, 25, 26, 27, 28, 29, 30, 31, 32, 33, 34, 35, 36, 37, 38, 39, 40, 41, 42, 43, 44, 45, 46, 47, 48, 49, 50, 51, 52, 53, 54, 55, 56, 57, 58, 59, 60

## CON_ERx8-060-01-L-D-RA-L-TR
designator CN?
pins: 0, 1, 2, 3, 4, 5, 6, 7, 8, 9, 10, 11, 12, 13, 14, 15, 16, 17, 18, 19, 20, 21, 22, 23, 24, 25, 26, 27, 28, 29, 30, 31, 32, 33, 34, 35, 36, 37, 38, 39, 40, 41, 42, 43, 44, 45, 46, 47, 48, 49, 50, 51, 52, 53, 54, 55, 56, 57, 58, 59, 60, 61, 62, 63, 64, 65, 66, 67, 68, 69, 70, 71, 72, 73, 74, 75, 76, 77, 78, 79, 80, 81, 82, 83, 84, 85, 86, 87, 88, 89, 90, 91, 92, 93, 94, 95, 96, 97, 98, 99, 100, 101, 102, 103, 104, 105, 106, 107, 108, 109, 110, 111, 112, 113, 114, 115, 116, 117, 118, 119, 120

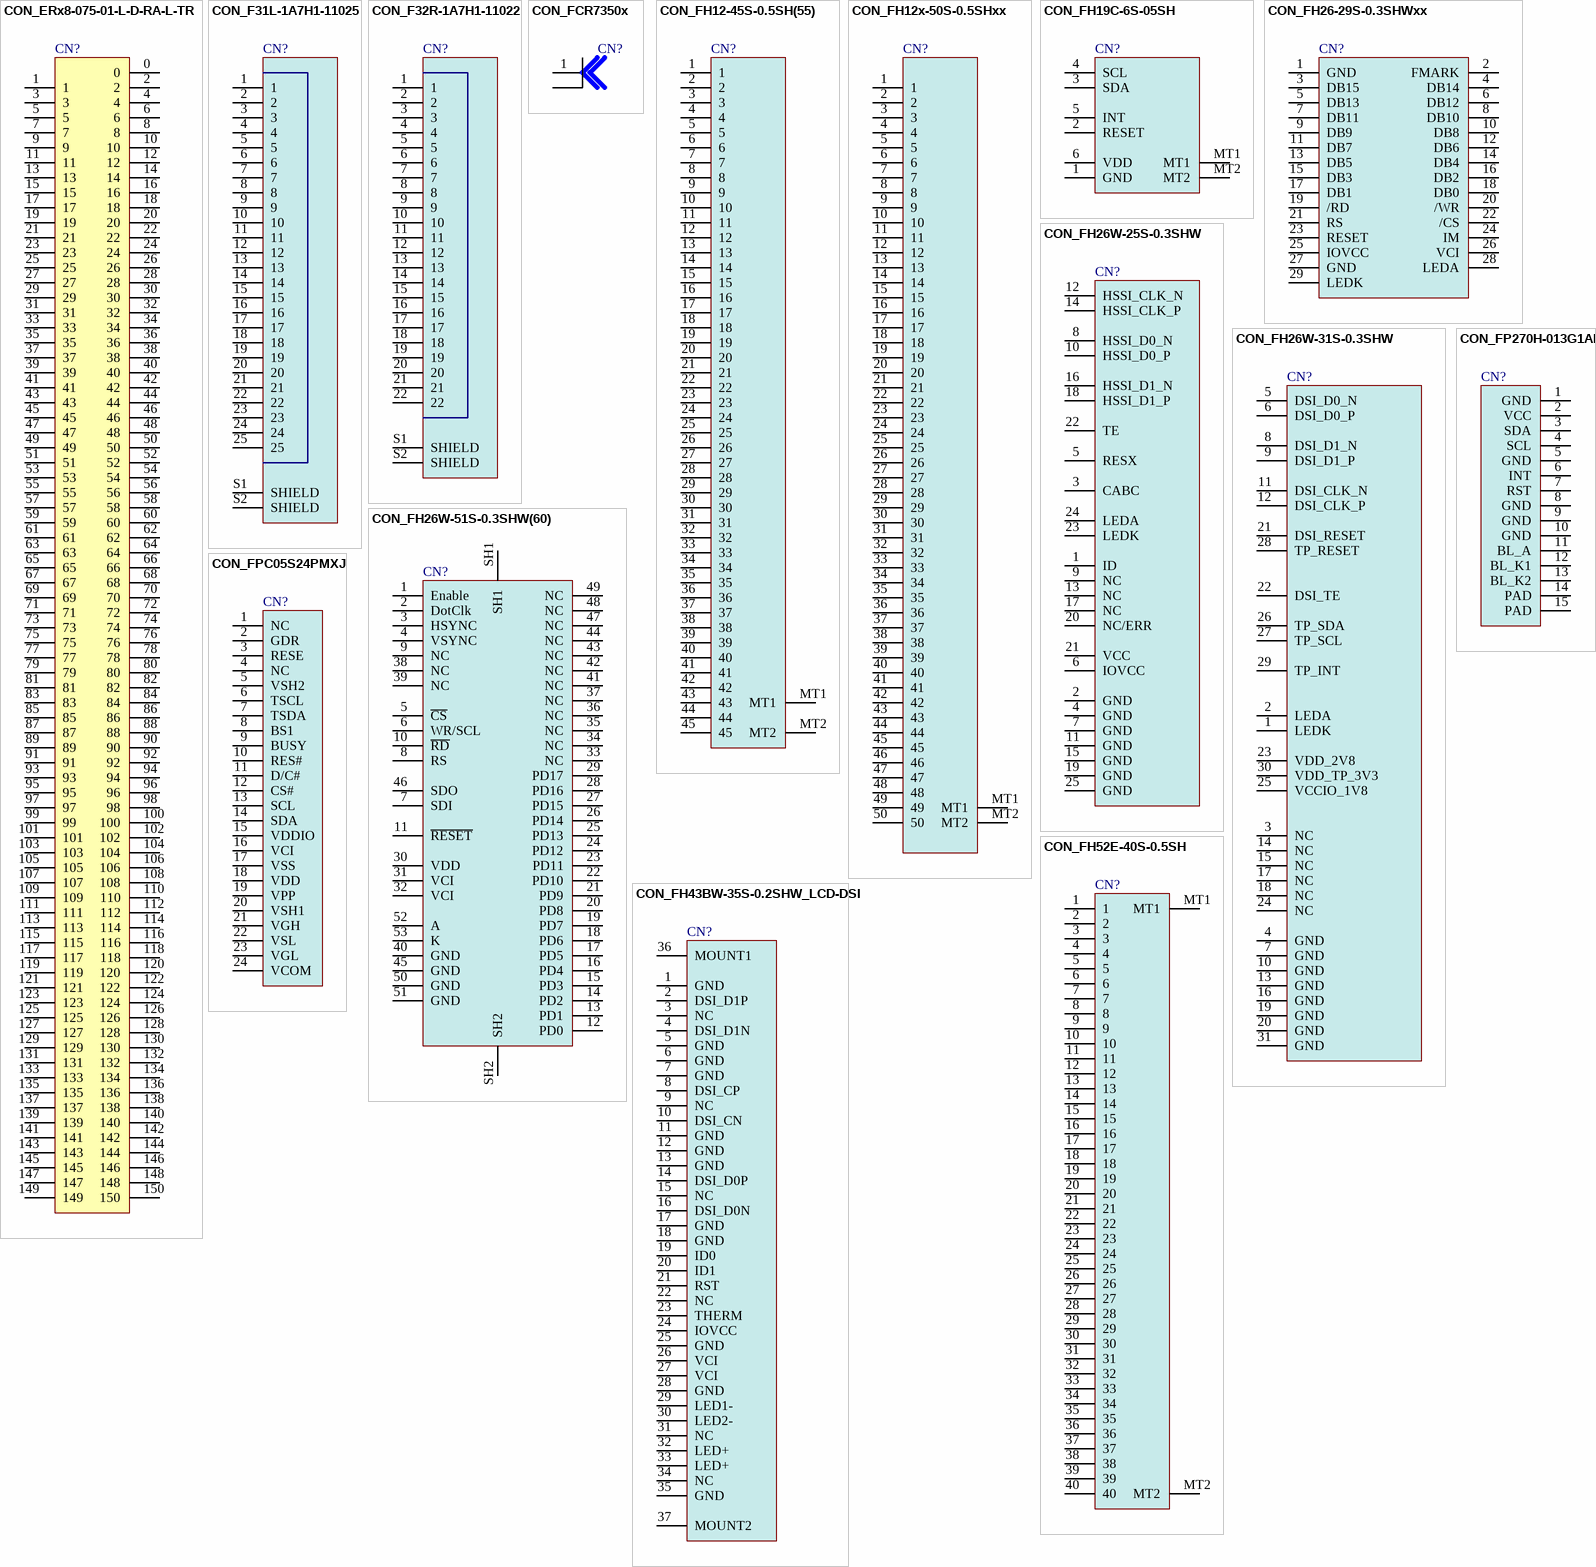
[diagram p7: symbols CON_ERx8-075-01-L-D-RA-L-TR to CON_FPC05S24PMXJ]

## CON_ERx8-075-01-L-D-RA-L-TR
designator CN?
pins: 0, 1, 2, 3, 4, 5, 6, 7, 8, 9, 10, 11, 12, 13, 14, 15, 16, 17, 18, 19, 20, 21, 22, 23, 24, 25, 26, 27, 28, 29, 30, 31, 32, 33, 34, 35, 36, 37, 38, 39, 40, 41, 42, 43, 44, 45, 46, 47, 48, 49, 50, 51, 52, 53, 54, 55, 56, 57, 58, 59, 60, 61, 62, 63, 64, 65, 66, 67, 68, 69, 70, 71, 72, 73, 74, 75, 76, 77, 78, 79, 80, 81, 82, 83, 84, 85, 86, 87, 88, 89, 90, 91, 92, 93, 94, 95, 96, 97, 98, 99, 100, 101, 102, 103, 104, 105, 106, 107, 108, 109, 110, 111, 112, 113, 114, 115, 116, 117, 118, 119, 120, 121, 122, 123, 124, 125, 126, 127, 128, 129, 130, 131, 132, 133, 134, 135, 136, 137, 138, 139, 140, 141, 142, 143, 144, 145, 146, 147, 148, 149, 150

## CON_F31L-1A7H1-11025
designator CN?
pins: 1, 2, 3, 4, 5, 6, 7, 8, 9, 10, 11, 12, 13, 14, 15, 16, 17, 18, 19, 20, 21, 22, 23, 24, 25, S1 SHIELD, S2 SHIELD

## CON_F32R-1A7H1-11022
designator CN?
pins: 1, 2, 3, 4, 5, 6, 7, 8, 9, 10, 11, 12, 13, 14, 15, 16, 17, 18, 19, 20, 21, 22, S1 SHIELD, S2 SHIELD

## CON_FCR7350x
designator CN?
pins: 0 (power), 1

## CON_FH12-45S-0.5SH(55)
designator CN?
pins: 1, 2, 3, 4, 5, 6, 7, 8, 9, 10, 11, 12, 13, 14, 15, 16, 17, 18, 19, 20, 21, 22, 23, 24, 25, 26, 27, 28, 29, 30, 31, 32, 33, 34, 35, 36, 37, 38, 39, 40, 41, 42, 43, 44, 45, MT1, MT2

## CON_FH12x-50S-0.5SHxx
designator CN?
pins: 1, 2, 3, 4, 5, 6, 7, 8, 9, 10, 11, 12, 13, 14, 15, 16, 17, 18, 19, 20, 21, 22, 23, 24, 25, 26, 27, 28, 29, 30, 31, 32, 33, 34, 35, 36, 37, 38, 39, 40, 41, 42, 43, 44, 45, 46, 47, 48, 49, 50, MT1, MT2

## CON_FH19C-6S-05SH
designator CN?
pins: 1 GND, 2 RESET, 3 SDA, 4 SCL, 5 INT, 6 VDD, MT1, MT2

## CON_FH26-29S-0.3SHWxx
designator CN?
pins: 1 GND, 2 FMARK, 3 DB15, 4 DB14, 5 DB13, 6 DB12, 7 DB11, 8 DB10, 9 DB9, 10 DB8, 11 DB7, 12 DB6, 13 DB5, 14 DB4, 15 DB3, 16 DB2, 17 DB1, 18 DB0, 19 /RD, 20 /WR, 21 RS, 22 /CS, 23 RESET, 24 IM, 25 IOVCC, 26 VCI, 27 GND, 28 LEDA, 29 LEDK

## CON_FH26W-25S-0.3SHW
designator CN?
pins: 1 ID, 2 GND, 3 CABC, 4 GND, 5 RESX, 6 IOVCC, 7 GND, 8 HSSI_D0_N, 9 NC, 10 HSSI_D0_P, 11 GND, 12 HSSI_CLK_N, 13 NC, 14 HSSI_CLK_P, 15 GND, 16 HSSI_D1_N, 17 NC, 18 HSSI_D1_P, 19 GND, 20 NC/ERR, 21 VCC, 22 TE, 23 LEDK, 24 LEDA, 25 GND

## CON_FH26W-31S-0.3SHW
designator CN?
pins: 1 LEDK, 2 LEDA, 3 NC, 4 GND, 5 DSI_D0_N, 6 DSI_D0_P, 7 GND, 8 DSI_D1_N, 9 DSI_D1_P, 10 GND, 11 DSI_CLK_N, 12 DSI_CLK_P, 13 GND, 14 NC, 15 NC, 16 GND, 17 NC, 18 NC, 19 GND, 20 GND, 21 DSI_RESET, 22 DSI_TE, 23 VDD_2V8, 24 NC, 25 VCCIO_1V8, 26 TP_SDA, 27 TP_SCL, 28 TP_RESET, 29 TP_INT, 30 VDD_TP_3V3, 31 GND

## CON_FH26W-51S-0.3SHW(60)
designator CN?
pins: 1 Enable, 2 DotClk, 3 HSYNC, 4 VSYNC, 5 ~{CS}, 6 WR/SCL, 7 SDI, 8 RS, 9 NC, 10 ~{RD}, 11 ~{RESET}, 12 PD0, 13 PD1, 14 PD2, 15 PD3, 16 PD4, 17 PD5, 18 PD6, 19 PD7, 20 PD8, 21 PD9, 22 PD10, 23 PD11, 24 PD12, 25 PD13, 26 PD14, 27 PD15, 28 PD16, 29 PD17, 30 VDD, 31 VCI, 32 VCI, 33 NC, 34 NC, 35 NC, 36 NC, 37 NC, 38 NC, 39 NC, 40 GND, 41 NC, 42 NC, 43 NC, 44 NC, 45 GND, 46 SDO, 47 NC, 48 NC, 49 NC, 50 GND, 51 GND, 52 A, 53 K, SH1, SH2

## CON_FH43BW-35S-0.2SHW_LCD-DSI
designator CN?
pins: 1 GND, 2 DSI_D1P, 3 NC, 4 DSI_D1N, 5 GND, 6 GND, 7 GND, 8 DSI_CP, 9 NC, 10 DSI_CN, 11 GND, 12 GND, 13 GND, 14 DSI_D0P, 15 NC, 16 DSI_D0N, 17 GND, 18 GND, 19 ID0, 20 ID1, 21 RST, 22 NC, 23 THERM, 24 IOVCC, 25 GND, 26 VCI, 27 VCI, 28 GND, 29 LED1-, 30 LED2-, 31 NC, 32 LED+, 33 LED+, 34 NC, 35 GND, 36 MOUNT1, 37 MOUNT2

## CON_FH52E-40S-0.5SH
designator CN?
pins: 1, 2, 3, 4, 5, 6, 7, 8, 9, 10, 11, 12, 13, 14, 15, 16, 17, 18, 19, 20, 21, 22, 23, 24, 25, 26, 27, 28, 29, 30, 31, 32, 33, 34, 35, 36, 37, 38, 39, 40, MT1, MT2

## CON_FP270H-013G1AM
designator CN?
pins: 1 GND, 2 VCC, 3 SDA, 4 SCL, 5 GND, 6 INT, 7 RST, 8 GND, 9 GND, 10 GND, 11 BL_A, 12 BL_K1, 13 BL_K2, 14 PAD, 15 PAD

## CON_FPC05S24PMXJ
designator CN?
pins: 1 NC, 2 GDR, 3 RESE, 4 NC, 5 VSH2, 6 TSCL, 7 TSDA, 8 BS1, 9 BUSY, 10 RES#, 11 D/C#, 12 CS#, 13 SCL, 14 SDA, 15 VDDIO, 16 VCI, 17 VSS, 18 VDD, 19 VPP, 20 VSH1, 21 VGH, 22 VSL, 23 VGL, 24 VCOM

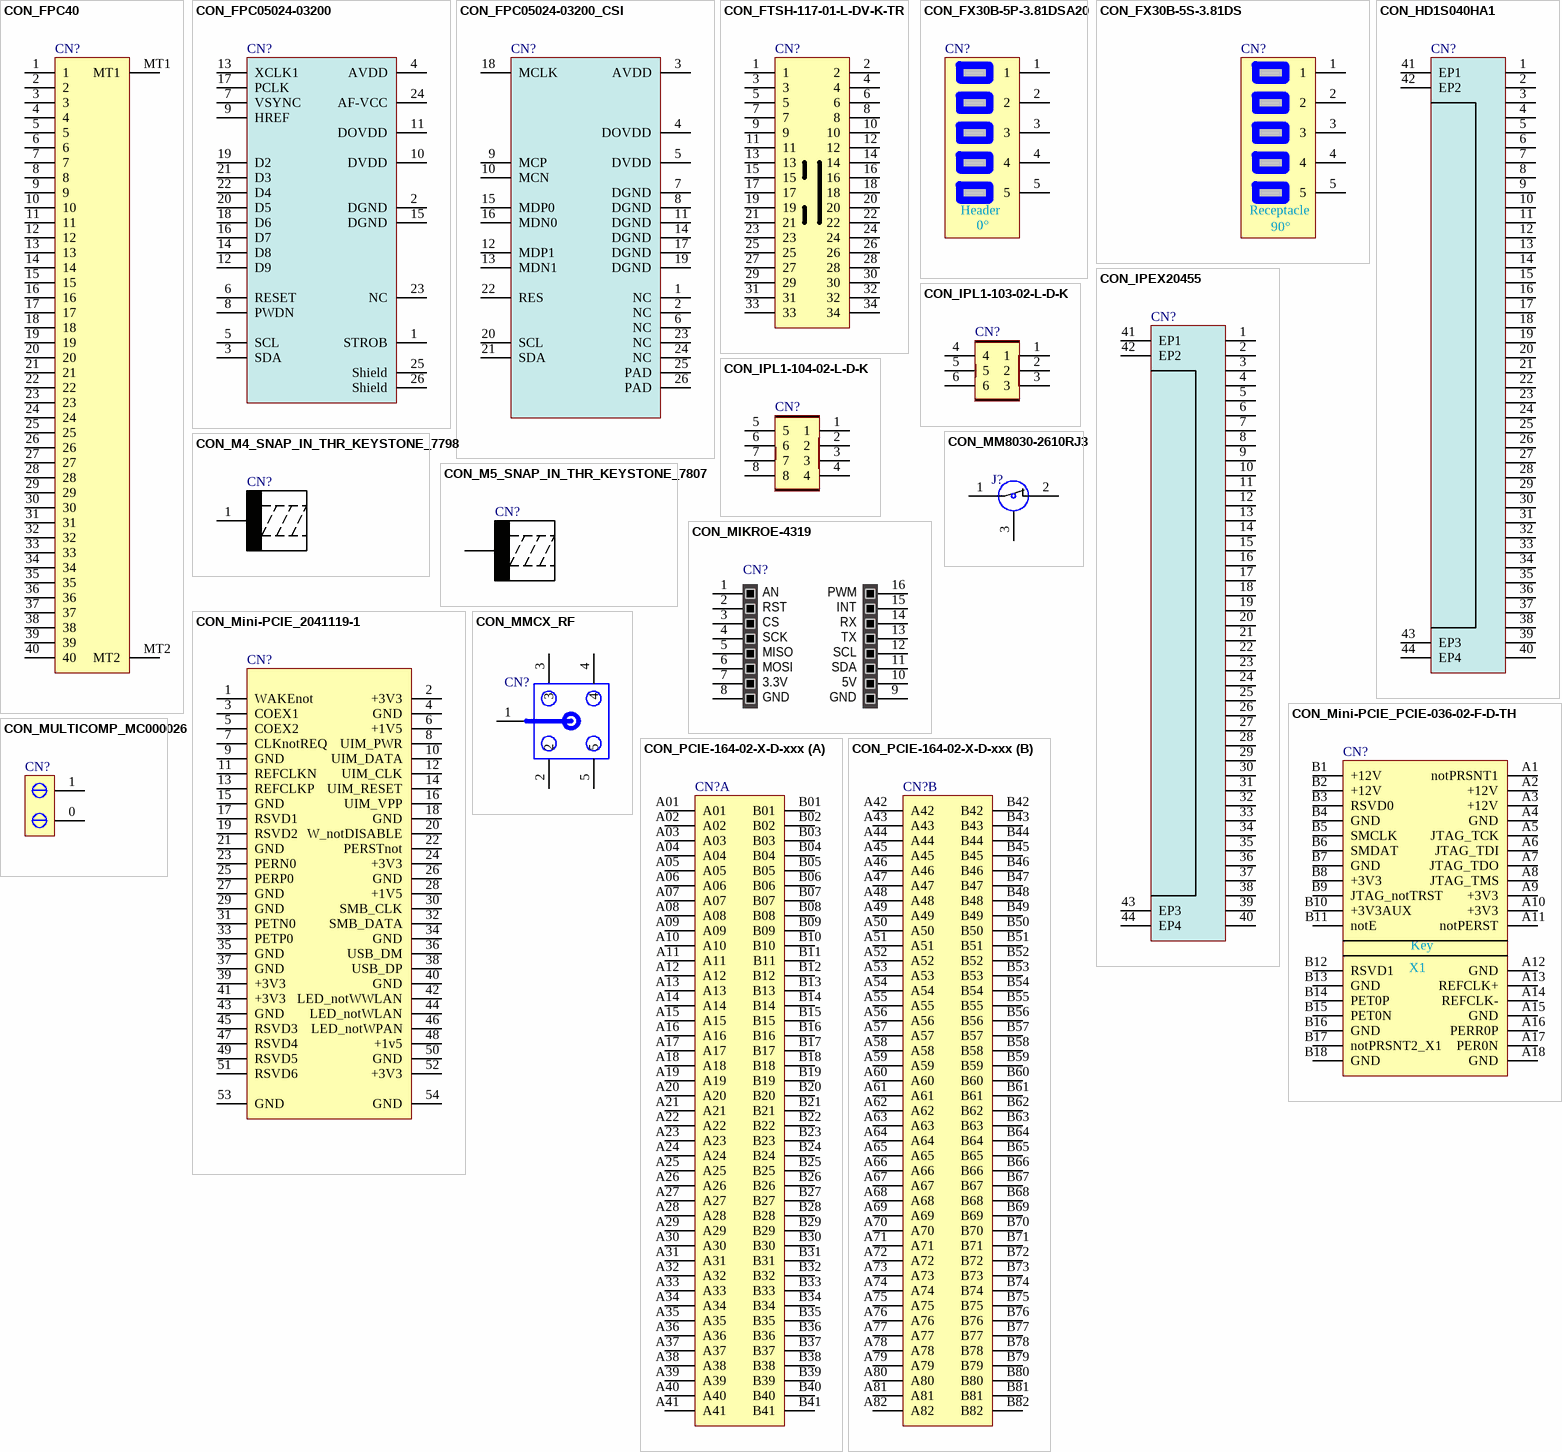
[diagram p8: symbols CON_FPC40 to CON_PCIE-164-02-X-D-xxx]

## CON_FPC40
designator CN?
pins: 1, 2, 3, 4, 5, 6, 7, 8, 9, 10, 11, 12, 13, 14, 15, 16, 17, 18, 19, 20, 21, 22, 23, 24, 25, 26, 27, 28, 29, 30, 31, 32, 33, 34, 35, 36, 37, 38, 39, 40, MT1, MT2

## CON_FPC05024-03200
designator CN?
pins: 1 STROB, 2 DGND, 3 SDA, 4 AVDD, 5 SCL, 6 RESET, 7 VSYNC, 8 PWDN, 9 HREF, 10 DVDD, 11 DOVDD, 12 D9, 13 XCLK1, 14 D8, 15 DGND, 16 D7, 17 PCLK, 18 D6, 19 D2, 20 D5, 21 D3, 22 D4, 23 NC, 24 AF-VCC, 25 Shield, 26 Shield

## CON_FPC05024-03200_CSI
designator CN?
pins: 1 NC, 2 NC, 3 AVDD, 4 DOVDD, 5 DVDD, 6 NC, 7 DGND, 8 DGND, 9 MCP, 10 MCN, 11 DGND, 12 MDP1, 13 MDN1, 14 DGND, 15 MDP0, 16 MDN0, 17 DGND, 18 MCLK, 19 DGND, 20 SCL, 21 SDA, 22 RES, 23 NC, 24 NC, 25 PAD, 26 PAD

## CON_FTSH-117-01-L-DV-K-TR
designator CN?
pins: 1, 2, 3, 4, 5, 6, 7, 8, 9, 10, 11, 12, 13, 14, 15, 16, 17, 18, 19, 20, 21, 22, 23, 24, 25, 26, 27, 28, 29, 30, 31, 32, 33, 34

## CON_FX30B-5P-3.81DSA20
designator CN?
pins: 1, 2, 3, 4, 5

## CON_FX30B-5S-3.81DS
designator CN?
pins: 1, 2, 3, 4, 5

## CON_HD1S040HA1
designator CN?
pins: 1, 2, 3, 4, 5, 6, 7, 8, 9, 10, 11, 12, 13, 14, 15, 16, 17, 18, 19, 20, 21, 22, 23, 24, 25, 26, 27, 28, 29, 30, 31, 32, 33, 34, 35, 36, 37, 38, 39, 40, 41 EP1, 42 EP2, 43 EP3, 44 EP4
1 alternate drawing of the same symbol

## CON_IPEX20455
designator CN?
pins: 1, 2, 3, 4, 5, 6, 7, 8, 9, 10, 11, 12, 13, 14, 15, 16, 17, 18, 19, 20, 21, 22, 23, 24, 25, 26, 27, 28, 29, 30, 31, 32, 33, 34, 35, 36, 37, 38, 39, 40, 41 EP1, 42 EP2, 43 EP3, 44 EP4
1 alternate drawing of the same symbol

## CON_IPL1-103-02-L-D-K
designator CN?
pins: 1, 2, 3, 4, 5, 6

## CON_IPL1-104-02-L-D-K
designator CN?
pins: 1, 2, 3, 4, 5, 6, 7, 8

## CON_M4_SNAP_IN_THR_KEYSTONE_7798
designator CN?
pins: 1

## CON_M5_SNAP_IN_THR_KEYSTONE_7807
designator CN?
pins: 1

## CON_MIKROE-4319
designator CN?
pins: 1, 2, 3, 4, 5, 6, 7, 8, 9, 10, 11, 12, 13, 14, 15, 16

## CON_Mini-PCIE_2041119-1
designator CN?
pins: 1 WAKEnot, 2 +3V3, 3 COEX1, 4 GND, 5 COEX2, 6 +1V5, 7 CLKnotREQ, 8 UIM_PWR, 9 GND, 10 UIM_DATA, 11 REFCLKN, 12 UIM_CLK, 13 REFCLKP, 14 UIM_RESET, 15 GND, 16 UIM_VPP, 17 RSVD1, 18 GND, 19 RSVD2, 20 W_notDISABLE, 21 GND, 22 PERSTnot, 23 PERN0, 24 +3V3, 25 PERP0, 26 GND, 27 GND, 28 +1V5, 29 GND, 30 SMB_CLK, 31 PETN0, 32 SMB_DATA, 33 PETP0, 34 GND, 35 GND, 36 USB_DM, 37 GND, 38 USB_DP, 39 +3V3, 40 GND, 41 +3V3, 42 LED_notWWLAN, 43 GND, 44 LED_notWLAN, 45 RSVD3, 46 LED_notWPAN, 47 RSVD4, 48 +1v5, 49 RSVD5, 50 GND, 51 RSVD6, 52 +3V3, 53 GND, 54 GND

## CON_Mini-PCIE_PCIE-036-02-F-D-TH
designator CN?
pins: A1 notPRSNT1, A2 +12V, A3 +12V, A4 GND, A5 JTAG_TCK, A6 JTAG_TDI, A7 JTAG_TDO, A8 JTAG_TMS, A9 +3V3, A10 +3V3, A11 notPERST, A12 GND, A13 REFCLK+, A14 REFCLK-, A15 GND, A16 PERR0P, A17 PER0N, A18 GND, B1 +12V, B2 +12V, B3 RSVD0, B4 GND, B5 SMCLK, B6 SMDAT, B7 GND, B8 +3V3, B9 JTAG_notTRST, B10 +3V3AUX, B11 notE, B12 RSVD1, B13 GND, B14 PET0P, B15 PET0N, B16 GND, B17 notPRSNT2_X1, B18 GND

## CON_MM8030-2610RJ3
designator J?
pins: 1 IN, 2 OUT, 3 GND

## CON_MMCX_RF
designator CN?
pins: 1, 2, 3, 4, 5

## CON_MULTICOMP_MC000026
designator CN?
pins: 0, 1

## CON_PCIE-164-02-X-D-xxx
designator CN?
part A pins: A01, A02, A03, A04, A05, A06, A07, A08, A09, A10, A11, A12, A13, A14, A15, A16, A17, A18, A19, A20, A21, A22, A23, A24, A25, A26, A27, A28, A29, A30, A31, A32, A33, A34, A35, A36, A37, A38, A39, A40, A41, B01, B02, B03, B04, B05, B06, B07, B08, B09, B10, B11, B12, B13, B14, B15, B16, B17, B18, B19, B20, B21, B22, B23, B24, B25, B26, B27, B28, B29, B30, B31, B32, B33, B34, B35, B36, B37, B38, B39, B40, B41
part B pins: A42, A43, A44, A45, A46, A47, A48, A49, A50, A51, A52, A53, A54, A55, A56, A57, A58, A59, A60, A61, A62, A63, A64, A65, A66, A67, A68, A69, A70, A71, A72, A73, A74, A75, A76, A77, A78, A79, A80, A81, A82, B42, B43, B44, B45, B46, B47, B48, B49, B50, B51, B52, B53, B54, B55, B56, B57, B58, B59, B60, B61, B62, B63, B64, B65, B66, B67, B68, B69, B70, B71, B72, B73, B74, B75, B76, B77, B78, B79, B80, B81, B82

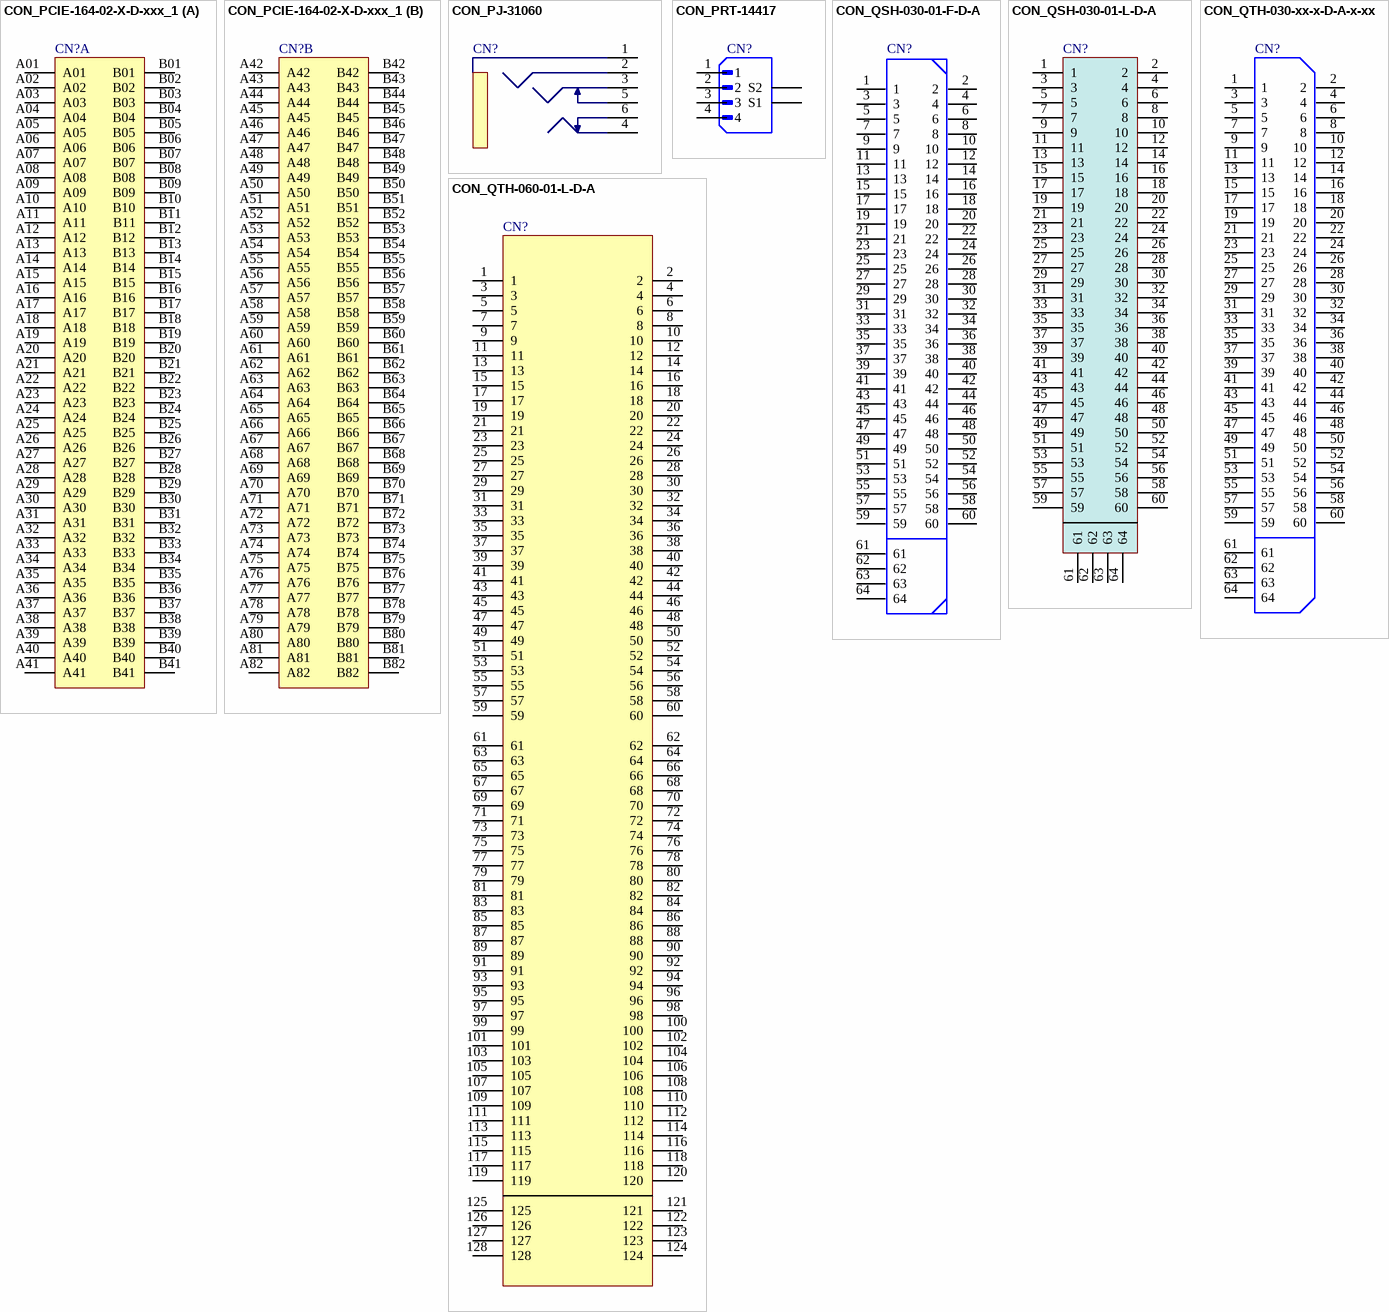
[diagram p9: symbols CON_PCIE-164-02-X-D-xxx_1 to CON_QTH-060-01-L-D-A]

## CON_PCIE-164-02-X-D-xxx_1
designator CN?
part A pins: A01, A02, A03, A04, A05, A06, A07, A08, A09, A10, A11, A12, A13, A14, A15, A16, A17, A18, A19, A20, A21, A22, A23, A24, A25, A26, A27, A28, A29, A30, A31, A32, A33, A34, A35, A36, A37, A38, A39, A40, A41, B01, B02, B03, B04, B05, B06, B07, B08, B09, B10, B11, B12, B13, B14, B15, B16, B17, B18, B19, B20, B21, B22, B23, B24, B25, B26, B27, B28, B29, B30, B31, B32, B33, B34, B35, B36, B37, B38, B39, B40, B41
part B pins: A42, A43, A44, A45, A46, A47, A48, A49, A50, A51, A52, A53, A54, A55, A56, A57, A58, A59, A60, A61, A62, A63, A64, A65, A66, A67, A68, A69, A70, A71, A72, A73, A74, A75, A76, A77, A78, A79, A80, A81, A82, B42, B43, B44, B45, B46, B47, B48, B49, B50, B51, B52, B53, B54, B55, B56, B57, B58, B59, B60, B61, B62, B63, B64, B65, B66, B67, B68, B69, B70, B71, B72, B73, B74, B75, B76, B77, B78, B79, B80, B81, B82

## CON_PJ-31060
designator CN?
pins: 1, 2, 3, 4, 5, 6

## CON_PRT-14417
designator CN?
pins: 1, 2, 3, 4, S1, S2

## CON_QSH-030-01-F-D-A
designator CN?
pins: 1, 2, 3, 4, 5, 6, 7, 8, 9, 10, 11, 12, 13, 14, 15, 16, 17, 18, 19, 20, 21, 22, 23, 24, 25, 26, 27, 28, 29, 30, 31, 32, 33, 34, 35, 36, 37, 38, 39, 40, 41, 42, 43, 44, 45, 46, 47, 48, 49, 50, 51, 52, 53, 54, 55, 56, 57, 58, 59, 60, 61, 62, 63, 64

## CON_QSH-030-01-L-D-A
designator CN?
pins: 1, 2, 3, 4, 5, 6, 7, 8, 9, 10, 11, 12, 13, 14, 15, 16, 17, 18, 19, 20, 21, 22, 23, 24, 25, 26, 27, 28, 29, 30, 31, 32, 33, 34, 35, 36, 37, 38, 39, 40, 41, 42, 43, 44, 45, 46, 47, 48, 49, 50, 51, 52, 53, 54, 55, 56, 57, 58, 59, 60, 61, 62, 63, 64

## CON_QTH-030-xx-x-D-A-x-xx
designator CN?
pins: 1, 2, 3, 4, 5, 6, 7, 8, 9, 10, 11, 12, 13, 14, 15, 16, 17, 18, 19, 20, 21, 22, 23, 24, 25, 26, 27, 28, 29, 30, 31, 32, 33, 34, 35, 36, 37, 38, 39, 40, 41, 42, 43, 44, 45, 46, 47, 48, 49, 50, 51, 52, 53, 54, 55, 56, 57, 58, 59, 60, 61, 62, 63, 64

## CON_QTH-060-01-L-D-A
designator CN?
pins: 1, 2, 3, 4, 5, 6, 7, 8, 9, 10, 11, 12, 13, 14, 15, 16, 17, 18, 19, 20, 21, 22, 23, 24, 25, 26, 27, 28, 29, 30, 31, 32, 33, 34, 35, 36, 37, 38, 39, 40, 41, 42, 43, 44, 45, 46, 47, 48, 49, 50, 51, 52, 53, 54, 55, 56, 57, 58, 59, 60, 61, 62, 63, 64, 65, 66, 67, 68, 69, 70, 71, 72, 73, 74, 75, 76, 77, 78, 79, 80, 81, 82, 83, 84, 85, 86, 87, 88, 89, 90, 91, 92, 93, 94, 95, 96, 97, 98, 99, 100, 101, 102, 103, 104, 105, 106, 107, 108, 109, 110, 111, 112, 113, 114, 115, 116, 117, 118, 119, 120, 121, 122, 123, 124, 125, 126, 127, 128

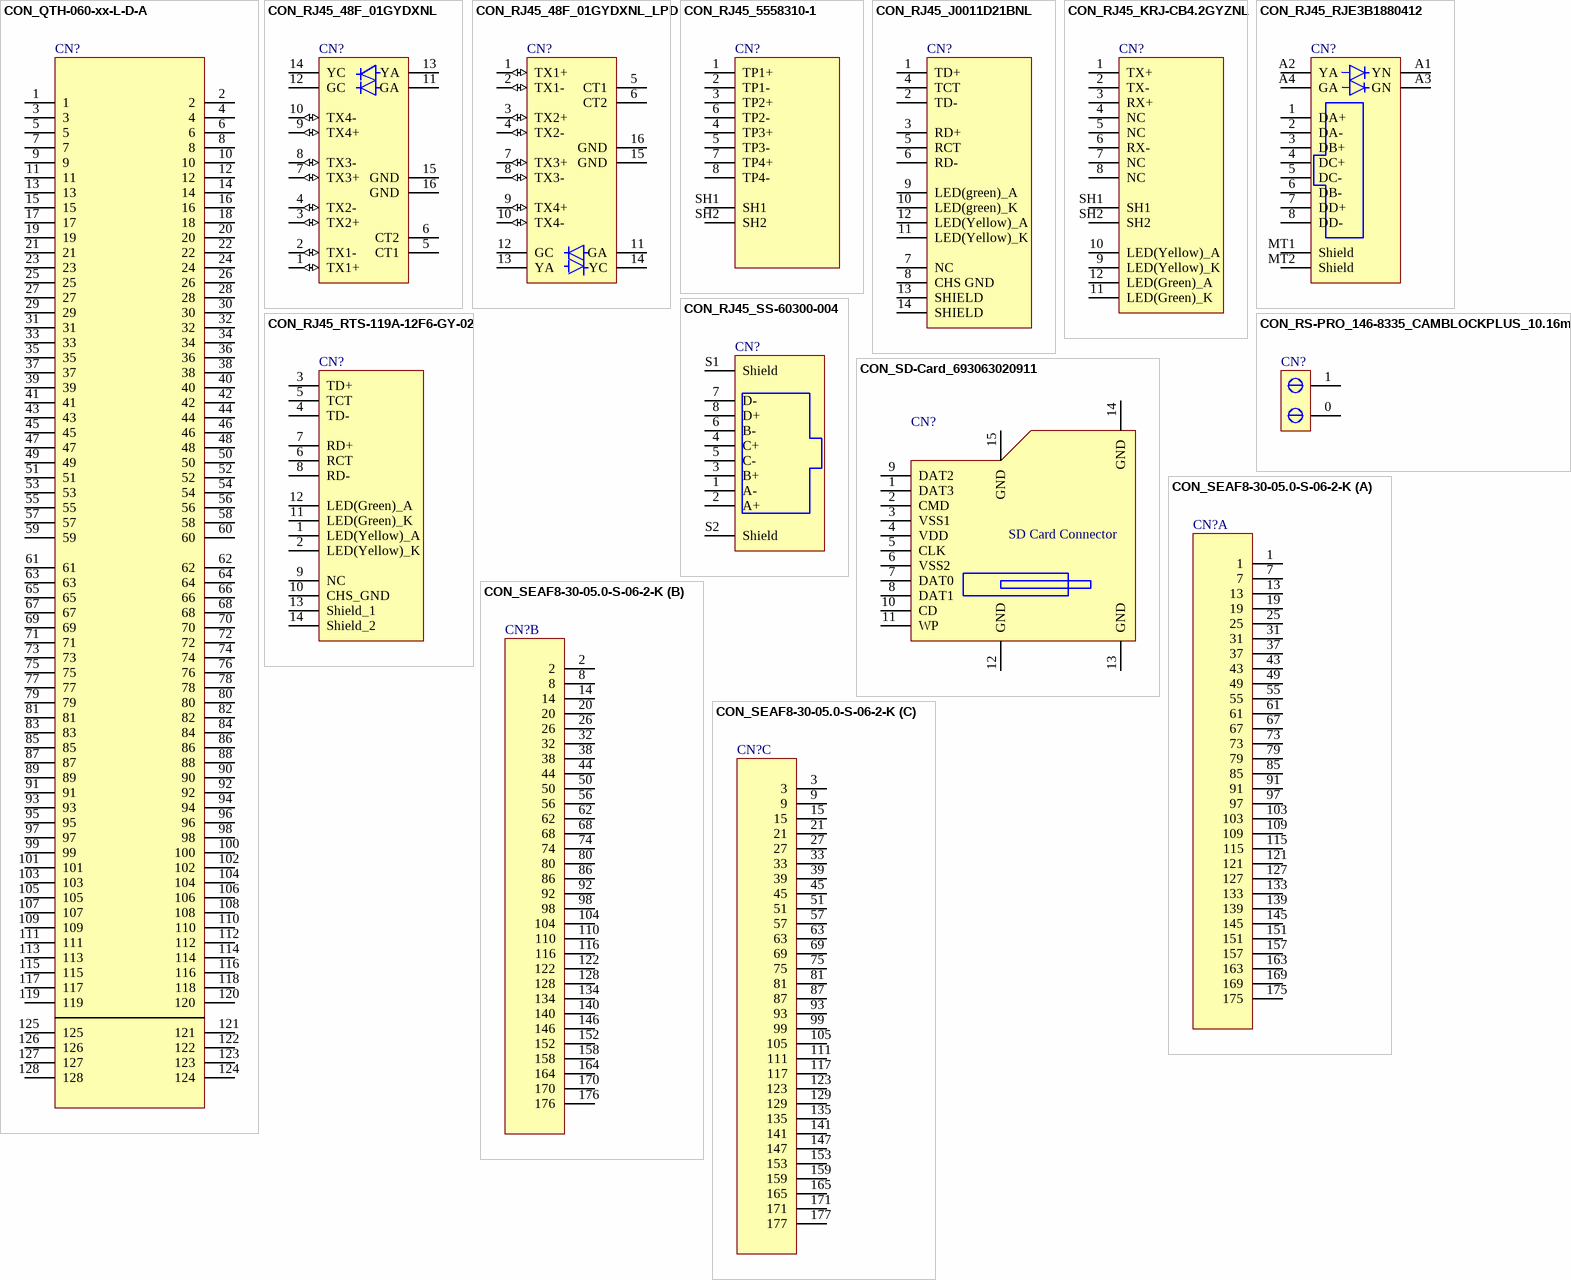
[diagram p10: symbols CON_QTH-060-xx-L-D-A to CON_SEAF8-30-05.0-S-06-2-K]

## CON_QTH-060-xx-L-D-A
designator CN?
pins: 1, 2, 3, 4, 5, 6, 7, 8, 9, 10, 11, 12, 13, 14, 15, 16, 17, 18, 19, 20, 21, 22, 23, 24, 25, 26, 27, 28, 29, 30, 31, 32, 33, 34, 35, 36, 37, 38, 39, 40, 41, 42, 43, 44, 45, 46, 47, 48, 49, 50, 51, 52, 53, 54, 55, 56, 57, 58, 59, 60, 61, 62, 63, 64, 65, 66, 67, 68, 69, 70, 71, 72, 73, 74, 75, 76, 77, 78, 79, 80, 81, 82, 83, 84, 85, 86, 87, 88, 89, 90, 91, 92, 93, 94, 95, 96, 97, 98, 99, 100, 101, 102, 103, 104, 105, 106, 107, 108, 109, 110, 111, 112, 113, 114, 115, 116, 117, 118, 119, 120, 121, 122, 123, 124, 125, 126, 127, 128

## CON_RJ45_48F_01GYDXNL
designator CN?
pins: 1 TX1+ (io), 2 TX1- (io), 3 TX2+ (io), 4 TX2- (io), 5 CT1, 6 CT2, 7 TX3+ (io), 8 TX3- (io), 9 TX4+ (io), 10 TX4- (io), 11 GA, 12 GC, 13 YA, 14 YC, 15 GND (power), 16 GND (power)

## CON_RJ45_48F_01GYDXNL_LPD
designator CN?
pins: 1 TX1+ (io), 2 TX1- (io), 3 TX2+ (io), 4 TX2- (io), 5 CT1, 6 CT2, 7 TX3+ (io), 8 TX3- (io), 9 TX4+ (io), 10 TX4- (io), 11 GA, 12 GC, 13 YA, 14 YC, 15 GND (power), 16 GND (power)

## CON_RJ45_5558310-1
designator CN?
pins: 1 TP1+, 2 TP1-, 3 TP2+, 4 TP3+, 5 TP3-, 6 TP2-, 7 TP4+, 8 TP4-, SH1, SH2

## CON_RJ45_J0011D21BNL
designator CN?
pins: 1 TD+, 2 TD-, 3 RD+, 4 TCT, 5 RCT, 6 RD-, 7 NC, 8 CHS GND, 9 LED(green)_A, 10 LED(green)_K, 11 LED(Yellow)_K, 12 LED(Yellow)_A, 13 SHIELD, 14 SHIELD

## CON_RJ45_KRJ-CB4.2GYZNL
designator CN?
pins: 1 TX+, 2 TX-, 3 RX+, 4 NC, 5 NC, 6 RX-, 7 NC, 8 NC, 9 LED(Yellow)_K, 10 LED(Yellow)_A, 11 LED(Green)_K, 12 LED(Green)_A, SH1, SH2
1 alternate drawing of the same symbol

## CON_RJ45_RJE3B1880412
designator CN?
pins: 1 DA+, 2 DA-, 3 DB+, 4 DC+, 5 DC-, 6 DB-, 7 DD+, 8 DD-, A1 YN, A2 YA, A3 GN, A4 GA, MT1 Shield, MT2 Shield

## CON_RJ45_RTS-119A-12F6-GY-02
designator CN?
pins: 1 LED(Yellow)_A, 2 LED(Yellow)_K, 3 TD+, 4 TD-, 5 TCT, 6 RCT, 7 RD+, 8 RD-, 9 NC, 10 CHS_GND, 11 LED(Green)_K, 12 LED(Green)_A, 13 Shield_1, 14 Shield_2
1 alternate drawing of the same symbol

## CON_RJ45_SS-60300-004
designator CN?
pins: 1 A-, 2 A+, 3 B+, 4 C+, 5 C-, 6 B-, 7 D-, 8 D+, S1 Shield, S2 Shield

## CON_RS-PRO_146-8335_CAMBLOCKPLUS_10.16mm_2P
designator CN?
pins: 0, 1

## CON_SD-Card_693063020911
designator CN?
pins: 1 DAT3, 2 CMD, 3 VSS1, 4 VDD, 5 CLK, 6 VSS2, 7 DAT0, 8 DAT1, 9 DAT2, 10 CD, 11 WP, 12 GND, 13 GND, 14 GND, 15 GND

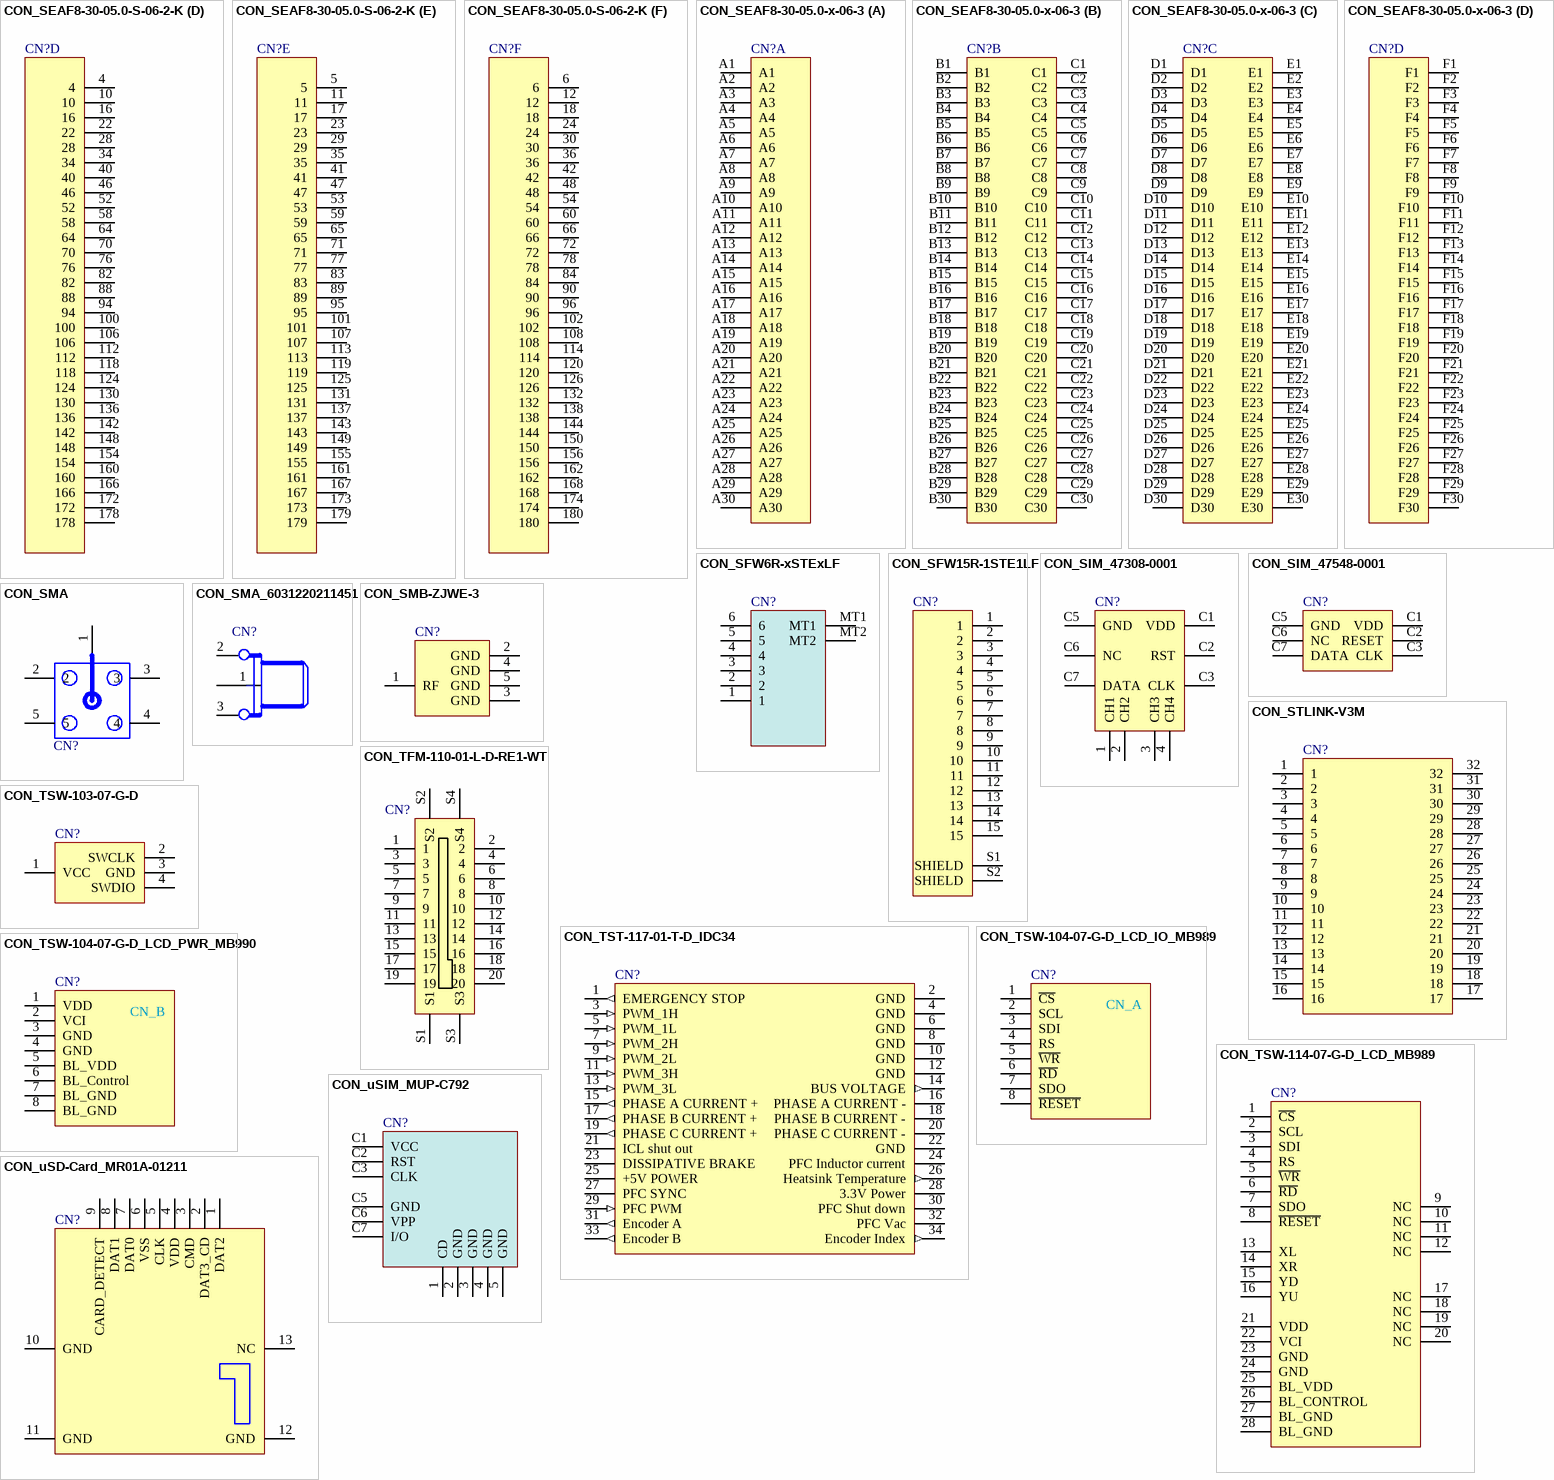
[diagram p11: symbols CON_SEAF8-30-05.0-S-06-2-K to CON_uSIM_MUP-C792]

## CON_SEAF8-30-05.0-S-06-2-K
designator CN?
part A pins: 1, 7, 13, 19, 25, 31, 37, 43, 49, 55, 61, 67, 73, 79, 85, 91, 97, 103, 109, 115, 121, 127, 133, 139, 145, 151, 157, 163, 169, 175
part B pins: 2, 8, 14, 20, 26, 32, 38, 44, 50, 56, 62, 68, 74, 80, 86, 92, 98, 104, 110, 116, 122, 128, 134, 140, 146, 152, 158, 164, 170, 176
part C pins: 3, 9, 15, 21, 27, 33, 39, 45, 51, 57, 63, 69, 75, 81, 87, 93, 99, 105, 111, 117, 123, 129, 135, 141, 147, 153, 159, 165, 171, 177
part D pins: 4, 10, 16, 22, 28, 34, 40, 46, 52, 58, 64, 70, 76, 82, 88, 94, 100, 106, 112, 118, 124, 130, 136, 142, 148, 154, 160, 166, 172, 178
part E pins: 5, 11, 17, 23, 29, 35, 41, 47, 53, 59, 65, 71, 77, 83, 89, 95, 101, 107, 113, 119, 125, 131, 137, 143, 149, 155, 161, 167, 173, 179
part F pins: 6, 12, 18, 24, 30, 36, 42, 48, 54, 60, 66, 72, 78, 84, 90, 96, 102, 108, 114, 120, 126, 132, 138, 144, 150, 156, 162, 168, 174, 180

## CON_SEAF8-30-05.0-x-06-3
designator CN?
part A pins: A1, A2, A3, A4, A5, A6, A7, A8, A9, A10, A11, A12, A13, A14, A15, A16, A17, A18, A19, A20, A21, A22, A23, A24, A25, A26, A27, A28, A29, A30
part B pins: B1, B2, B3, B4, B5, B6, B7, B8, B9, B10, B11, B12, B13, B14, B15, B16, B17, B18, B19, B20, B21, B22, B23, B24, B25, B26, B27, B28, B29, B30, C1, C2, C3, C4, C5, C6, C7, C8, C9, C10, C11, C12, C13, C14, C15, C16, C17, C18, C19, C20, C21, C22, C23, C24, C25, C26, C27, C28, C29, C30
part C pins: D1, D2, D3, D4, D5, D6, D7, D8, D9, D10, D11, D12, D13, D14, D15, D16, D17, D18, D19, D20, D21, D22, D23, D24, D25, D26, D27, D28, D29, D30, E1, E2, E3, E4, E5, E6, E7, E8, E9, E10, E11, E12, E13, E14, E15, E16, E17, E18, E19, E20, E21, E22, E23, E24, E25, E26, E27, E28, E29, E30
part D pins: F1, F2, F3, F4, F5, F6, F7, F8, F9, F10, F11, F12, F13, F14, F15, F16, F17, F18, F19, F20, F21, F22, F23, F24, F25, F26, F27, F28, F29, F30

## CON_SFW6R-xSTExLF
designator CN?
pins: 1, 2, 3, 4, 5, 6, MT1, MT2

## CON_SFW15R-1STE1LF
designator CN?
pins: 1, 2, 3, 4, 5, 6, 7, 8, 9, 10, 11, 12, 13, 14, 15, S1 SHIELD, S2 SHIELD

## CON_SIM_47308-0001
designator CN?
pins: 1 CH1, 2 CH2, 3 CH3, 4 CH4, C1 VDD, C2 RST, C3 CLK, C5 GND, C6 NC, C7 DATA

## CON_SIM_47548-0001
designator CN?
pins: C1 VDD, C2 RESET, C3 CLK, C5 GND, C6 NC, C7 DATA

## CON_SMA
designator CN?
pins: 1, 2, 3, 4, 5

## CON_SMA_6031220211451
designator CN?
pins: 1, 2, 3

## CON_SMB-ZJWE-3
designator CN?
pins: 1 RF, 2 GND, 3 GND, 4 GND, 5 GND

## CON_STLINK-V3M
designator CN?
pins: 1, 2, 3, 4, 5, 6, 7, 8, 9, 10, 11, 12, 13, 14, 15, 16, 17, 18, 19, 20, 21, 22, 23, 24, 25, 26, 27, 28, 29, 30, 31, 32

## CON_TFM-110-01-L-D-RE1-WT
designator CN?
pins: 1, 2, 3, 4, 5, 6, 7, 8, 9, 10, 11, 12, 13, 14, 15, 16, 17, 18, 19, 20, S1, S2, S3, S4
1 alternate drawing of the same symbol

## CON_TST-117-01-T-D_IDC34
designator CN?
pins: 1 EMERGENCY STOP (out), 2 GND (power), 3 PWM_1H (in), 4 GND (power), 5 PWM_1L (in), 6 GND (power), 7 PWM_2H (in), 8 GND (power), 9 PWM_2L (in), 10 GND (power), 11 PWM_3H (in), 12 GND (power), 13 PWM_3L (in), 14 BUS VOLTAGE (out), 15 PHASE A CURRENT + (out), 16 PHASE A CURRENT - (power), 17 PHASE B CURRENT + (out), 18 PHASE B CURRENT - (power), 19 PHASE C CURRENT + (out), 20 PHASE C CURRENT - (power), 21 ICL shut out, 22 GND (power), 23 DISSIPATIVE BRAKE, 24 PFC Inductor current, 25 +5V POWER (power), 26 Heatsink Temperature (out), 27 PFC SYNC, 28 3.3V Power (power), 29 PFC PWM (in), 30 PFC Shut down, 31 Encoder A (out), 32 PFC Vac, 33 Encoder B (out), 34 Encoder Index (out)

## CON_TSW-103-07-G-D
designator CN?
pins: 1 VCC, 2 SWCLK, 3 GND, 4 SWDIO

## CON_TSW-104-07-G-D_LCD_IO_MB989
designator CN?
pins: 1 ~{CS}, 2 SCL, 3 SDI, 4 RS, 5 ~{WR}, 6 ~{RD}, 7 SDO, 8 ~{RESET}

## CON_TSW-104-07-G-D_LCD_PWR_MB990
designator CN?
pins: 1 VDD, 2 VCI, 3 GND, 4 GND, 5 BL_VDD, 6 BL_Control, 7 BL_GND, 8 BL_GND

## CON_TSW-114-07-G-D_LCD_MB989
designator CN?
pins: 1 ~{CS}, 2 SCL, 3 SDI, 4 RS, 5 ~{WR}, 6 ~{RD}, 7 SDO, 8 ~{RESET}, 9 NC, 10 NC, 11 NC, 12 NC, 13 XL, 14 XR, 15 YD, 16 YU, 17 NC, 18 NC, 19 NC, 20 NC, 21 VDD, 22 VCI, 23 GND, 24 GND, 25 BL_VDD, 26 BL_CONTROL, 27 BL_GND, 28 BL_GND

## CON_uSD-Card_MR01A-01211
designator CN?
pins: 1 DAT2, 2 DAT3_CD, 3 CMD, 4 VDD, 5 CLK, 6 VSS, 7 DAT0, 8 DAT1, 9 CARD_DETECT, 10 GND, 11 GND, 12 GND, 13 NC

## CON_uSIM_MUP-C792
designator CN?
pins: 1 CD, 2 GND, 3 GND, 4 GND, 5 GND, C1 VCC, C2 RST, C3 CLK, C5 GND, C6 VPP, C7 I/O

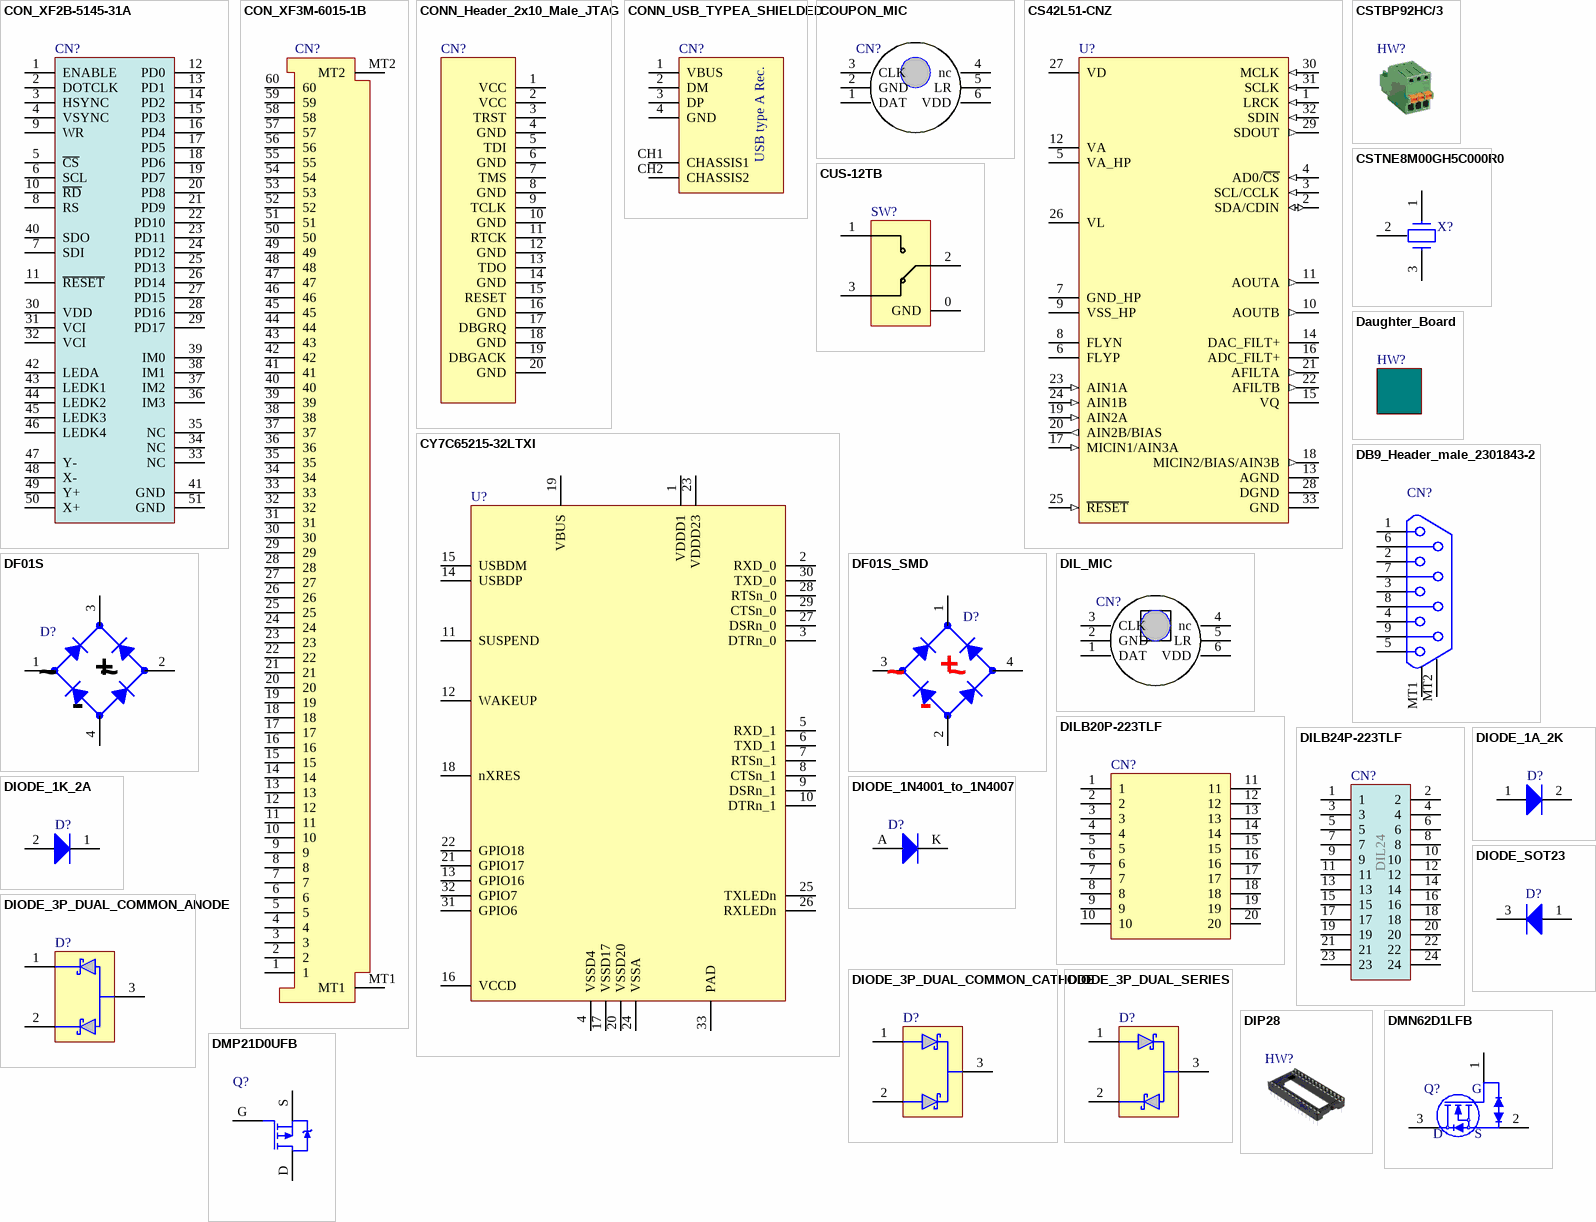
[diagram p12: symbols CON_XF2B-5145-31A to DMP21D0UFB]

## CON_XF2B-5145-31A
designator CN?
pins: 1 ENABLE, 2 DOTCLK, 3 HSYNC, 4 VSYNC, 5 ~{CS}, 6 SCL, 7 SDI, 8 RS, 9 WR, 10 ~{RD}, 11 ~{RESET}, 12 PD0, 13 PD1, 14 PD2, 15 PD3, 16 PD4, 17 PD5, 18 PD6, 19 PD7, 20 PD8, 21 PD9, 22 PD10, 23 PD11, 24 PD12, 25 PD13, 26 PD14, 27 PD15, 28 PD16, 29 PD17, 30 VDD, 31 VCI, 32 VCI, 33 NC, 34 NC, 35 NC, 36 IM3, 37 IM2, 38 IM1, 39 IM0, 40 SDO, 41 GND, 42 LEDA, 43 LEDK1, 44 LEDK2, 45 LEDK3, 46 LEDK4, 47 Y-, 48 X-, 49 Y+, 50 X+, 51 GND

## CON_XF3M-6015-1B
designator CN?
pins: 1, 2, 3, 4, 5, 6, 7, 8, 9, 10, 11, 12, 13, 14, 15, 16, 17, 18, 19, 20, 21, 22, 23, 24, 25, 26, 27, 28, 29, 30, 31, 32, 33, 34, 35, 36, 37, 38, 39, 40, 41, 42, 43, 44, 45, 46, 47, 48, 49, 50, 51, 52, 53, 54, 55, 56, 57, 58, 59, 60, MT1, MT2

## CONN_Header_2x10_Male_JTAG
designator CN?
pins: 1 VCC, 2 VCC, 3 TRST, 4 GND, 5 TDI, 6 GND, 7 TMS, 8 GND, 9 TCLK, 10 GND, 11 RTCK, 12 GND, 13 TDO, 14 GND, 15 RESET, 16 GND, 17 DBGRQ, 18 GND, 19 DBGACK, 20 GND

## CONN_USB_TYPEA_SHIELDED
designator CN?
pins: 1 VBUS, 2 DM, 3 DP, 4 GND, CH1 CHASSIS1, CH2 CHASSIS2

## COUPON_MIC
designator CN?
pins: 1 DAT, 2 GND, 3 CLK, 4 nc, 5 LR, 6 VDD

## CS42L51-CNZ
designator U?
pins: 1 LRCK (in), 2 SDA/CDIN (io), 3 SCL/CCLK (in), 4 AD0/~{CS} (in), 5 VA_HP (power), 6 FLYP, 7 GND_HP (power), 8 FLYN, 9 VSS_HP (power), 10 AOUTB (out), 11 AOUTA (out), 12 VA (power), 13 AGND (power), 14 DAC_FILT+ (power), 15 VQ (power), 16 ADC_FILT+ (power), 17 MICIN1/AIN3A (in), 18 MICIN2/BIAS/AIN3B (out), 19 AIN2A (in), 20 AIN2B/BIAS (out), 21 AFILTA (out), 22 AFILTB (out), 23 AIN1A (in), 24 AIN1B (in), 25 ~{RESET} (in), 26 VL (power), 27 VD (power), 28 DGND (power), 29 SDOUT (out), 30 MCLK (in), 31 SCLK (in), 32 SDIN (in), 33 GND (power)

## CSTBP92HC/3
designator HW?

## CSTNE8M00GH5C000R0
designator X?
pins: 1, 2, 3

## CUS-12TB
designator SW?
pins: 0 GND, 1, 2, 3

## CY7C65215-32LTXI
designator U?
pins: 1 VDDD1, 2 RXD_0, 3 DTRn_0, 4 VSSD4, 5 RXD_1, 6 TXD_1, 7 RTSn_1, 8 CTSn_1, 9 DSRn_1, 10 DTRn_1, 11 SUSPEND, 12 WAKEUP, 13 GPIO16, 14 USBDP, 15 USBDM, 16 VCCD, 17 VSSD17, 18 nXRES, 19 VBUS, 20 VSSD20, 21 GPIO17, 22 GPIO18, 23 VDDD23, 24 VSSA, 25 TXLEDn, 26 RXLEDn, 27 DSRn_0, 28 RTSn_0, 29 CTSn_0, 30 TXD_0, 31 GPIO6, 32 GPIO7, 33 PAD

## Daughter_Board
designator HW?

## DB9_Header_male_2301843-2
designator CN?
pins: 1, 2, 3, 4, 5, 6, 7, 8, 9, MT1, MT2

## DF01S
designator D?
pins: 1 AC IN 1, 2 AC IN 2, 3 DC OUT PLUS, 4 DC OUT MINUS

## DF01S_SMD
designator D?
pins: 1 DC OUT PLUS, 2 DC OUT MINUS, 3 AC IN 2, 4 AC IN 1

## DIL_MIC
designator CN?
pins: 1 DAT, 2 GND, 3 CLK, 4 nc, 5 LR, 6 VDD

## DILB20P-223TLF
designator CN?
pins: 1, 2, 3, 4, 5, 6, 7, 8, 9, 10, 11, 12, 13, 14, 15, 16, 17, 18, 19, 20

## DILB24P-223TLF
designator CN?
pins: 1, 2, 3, 4, 5, 6, 7, 8, 9, 10, 11, 12, 13, 14, 15, 16, 17, 18, 19, 20, 21, 22, 23, 24

## DIODE_1A_2K
designator D?
pins: 1 A, 2 K

## DIODE_1K_2A
designator D?
pins: 1 K, 2 A

## DIODE_1N4001_to_1N4007
designator D?
pins: A, K

## DIODE_3P_DUAL_COMMON_ANODE
designator D?
pins: 1, 2, 3

## DIODE_3P_DUAL_COMMON_CATHODE
designator D?
pins: 1, 2, 3

## DIODE_3P_DUAL_SERIES
designator D?
pins: 1, 2, 3

## DIODE_SOT23
designator D?
pins: 1 A, 3 K

## DIP28
designator HW?  (mechanical)

## DMN62D1LFB
designator Q?
pins: 1 G, 2 S, 3 D

## DMP21D0UFB
designator Q?
pins: D, G, S

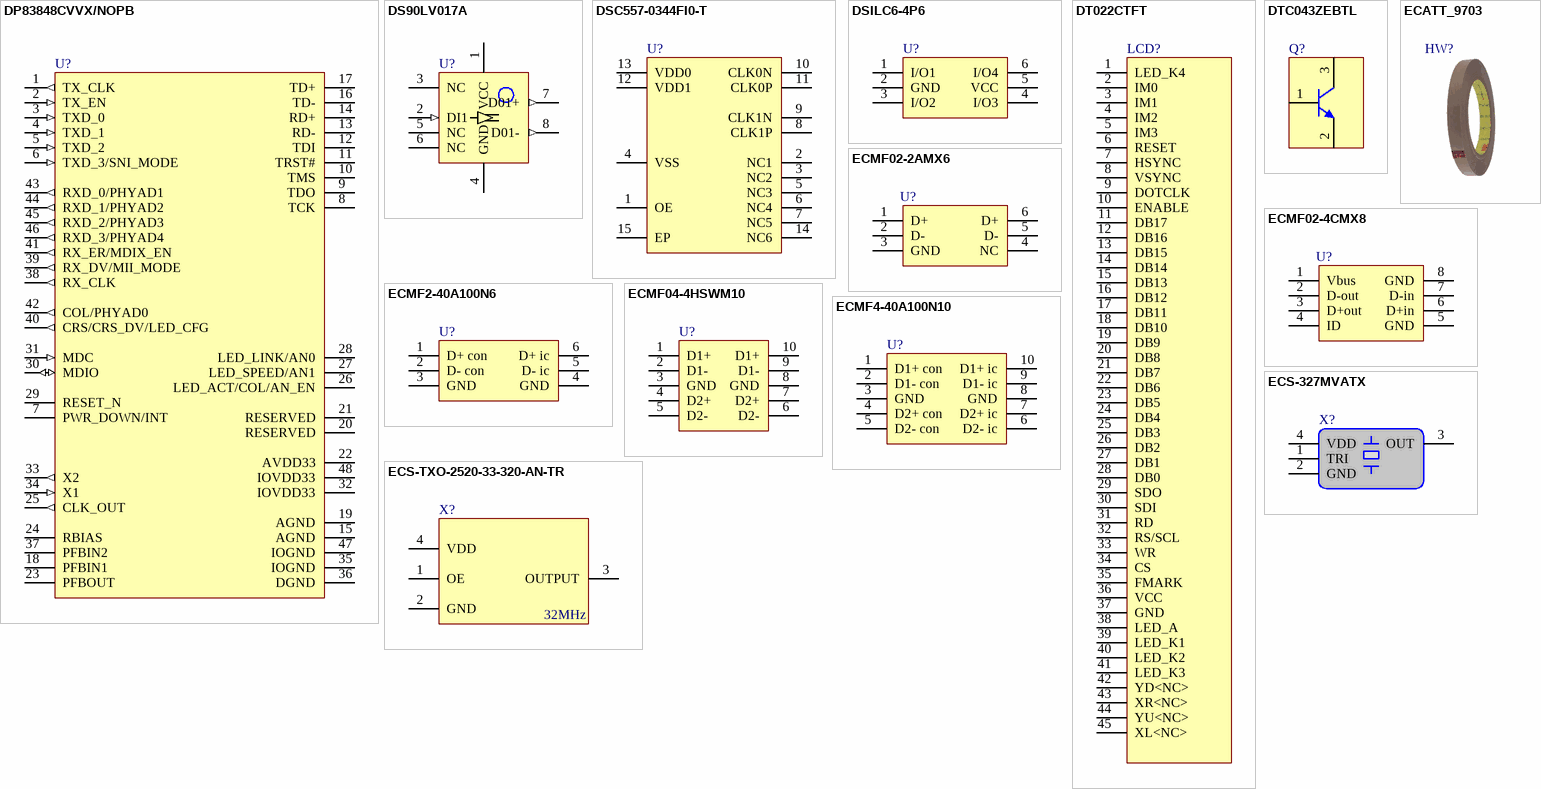
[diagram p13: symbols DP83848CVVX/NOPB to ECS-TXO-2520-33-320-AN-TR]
